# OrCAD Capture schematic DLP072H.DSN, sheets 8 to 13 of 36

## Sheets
8 PAGE10 - FPGA REGULATORS: size A3
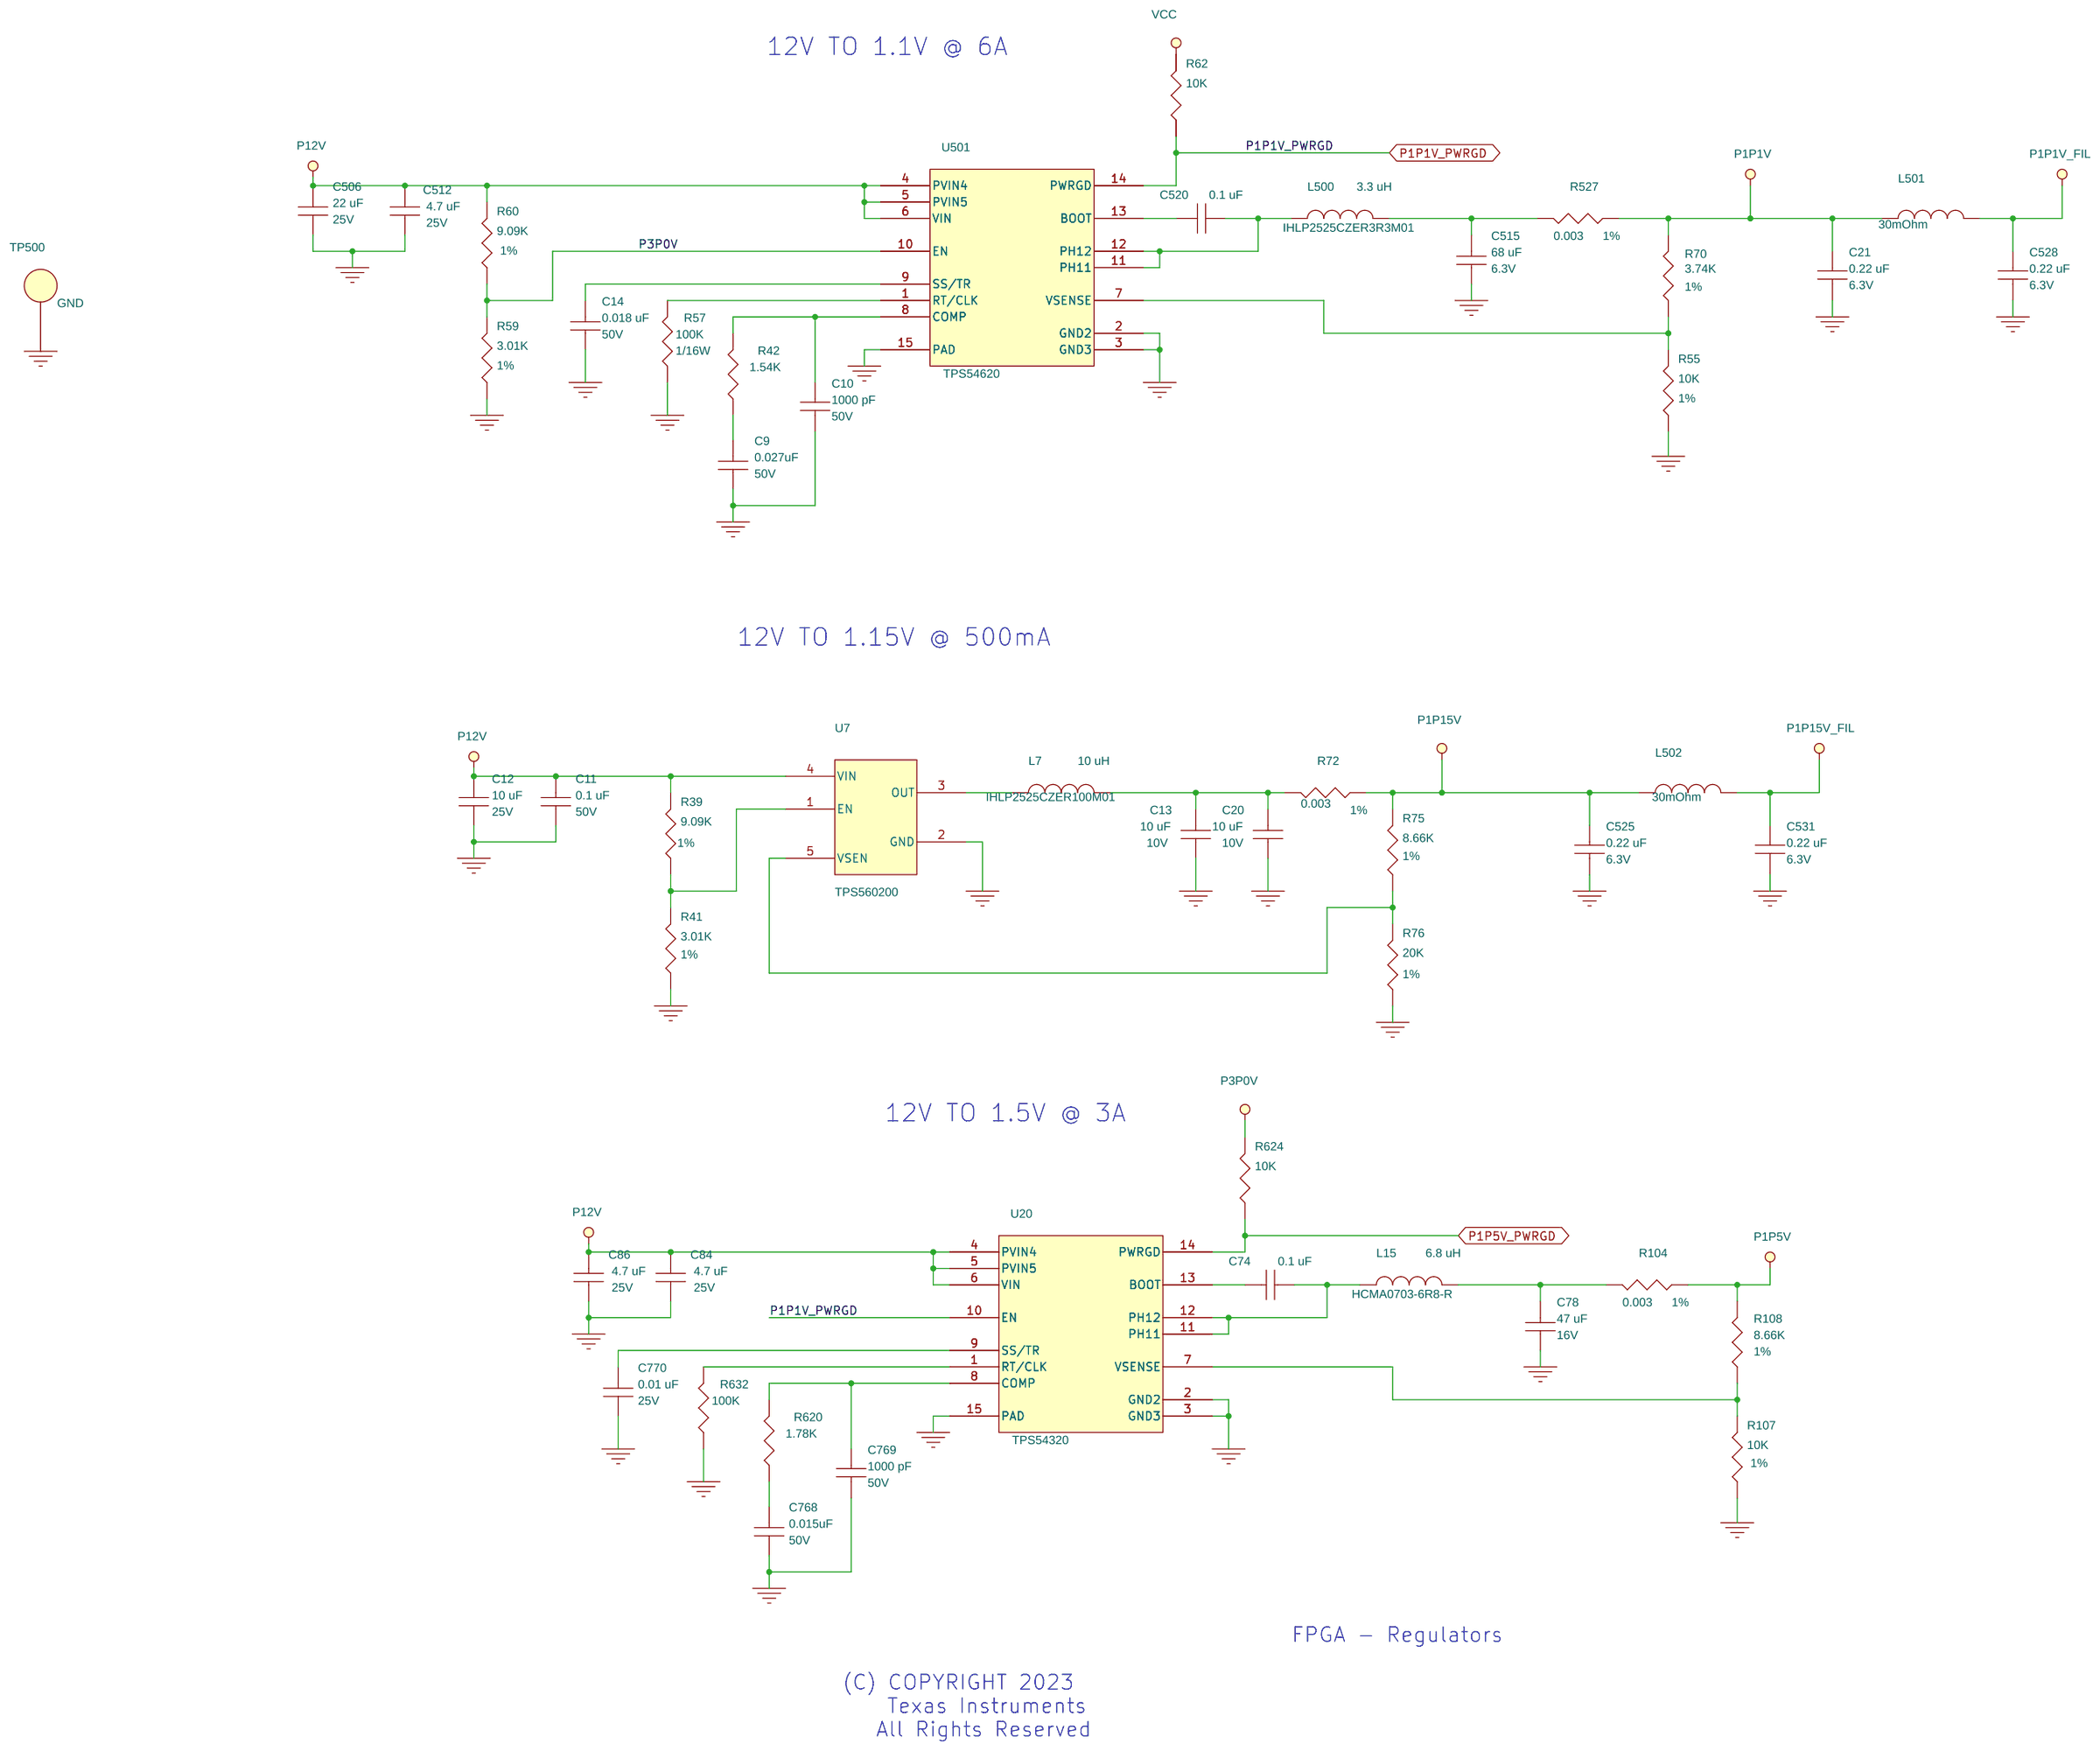
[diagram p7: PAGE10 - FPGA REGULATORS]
9 PAGE11 - FPGA REGULATORS: size A3
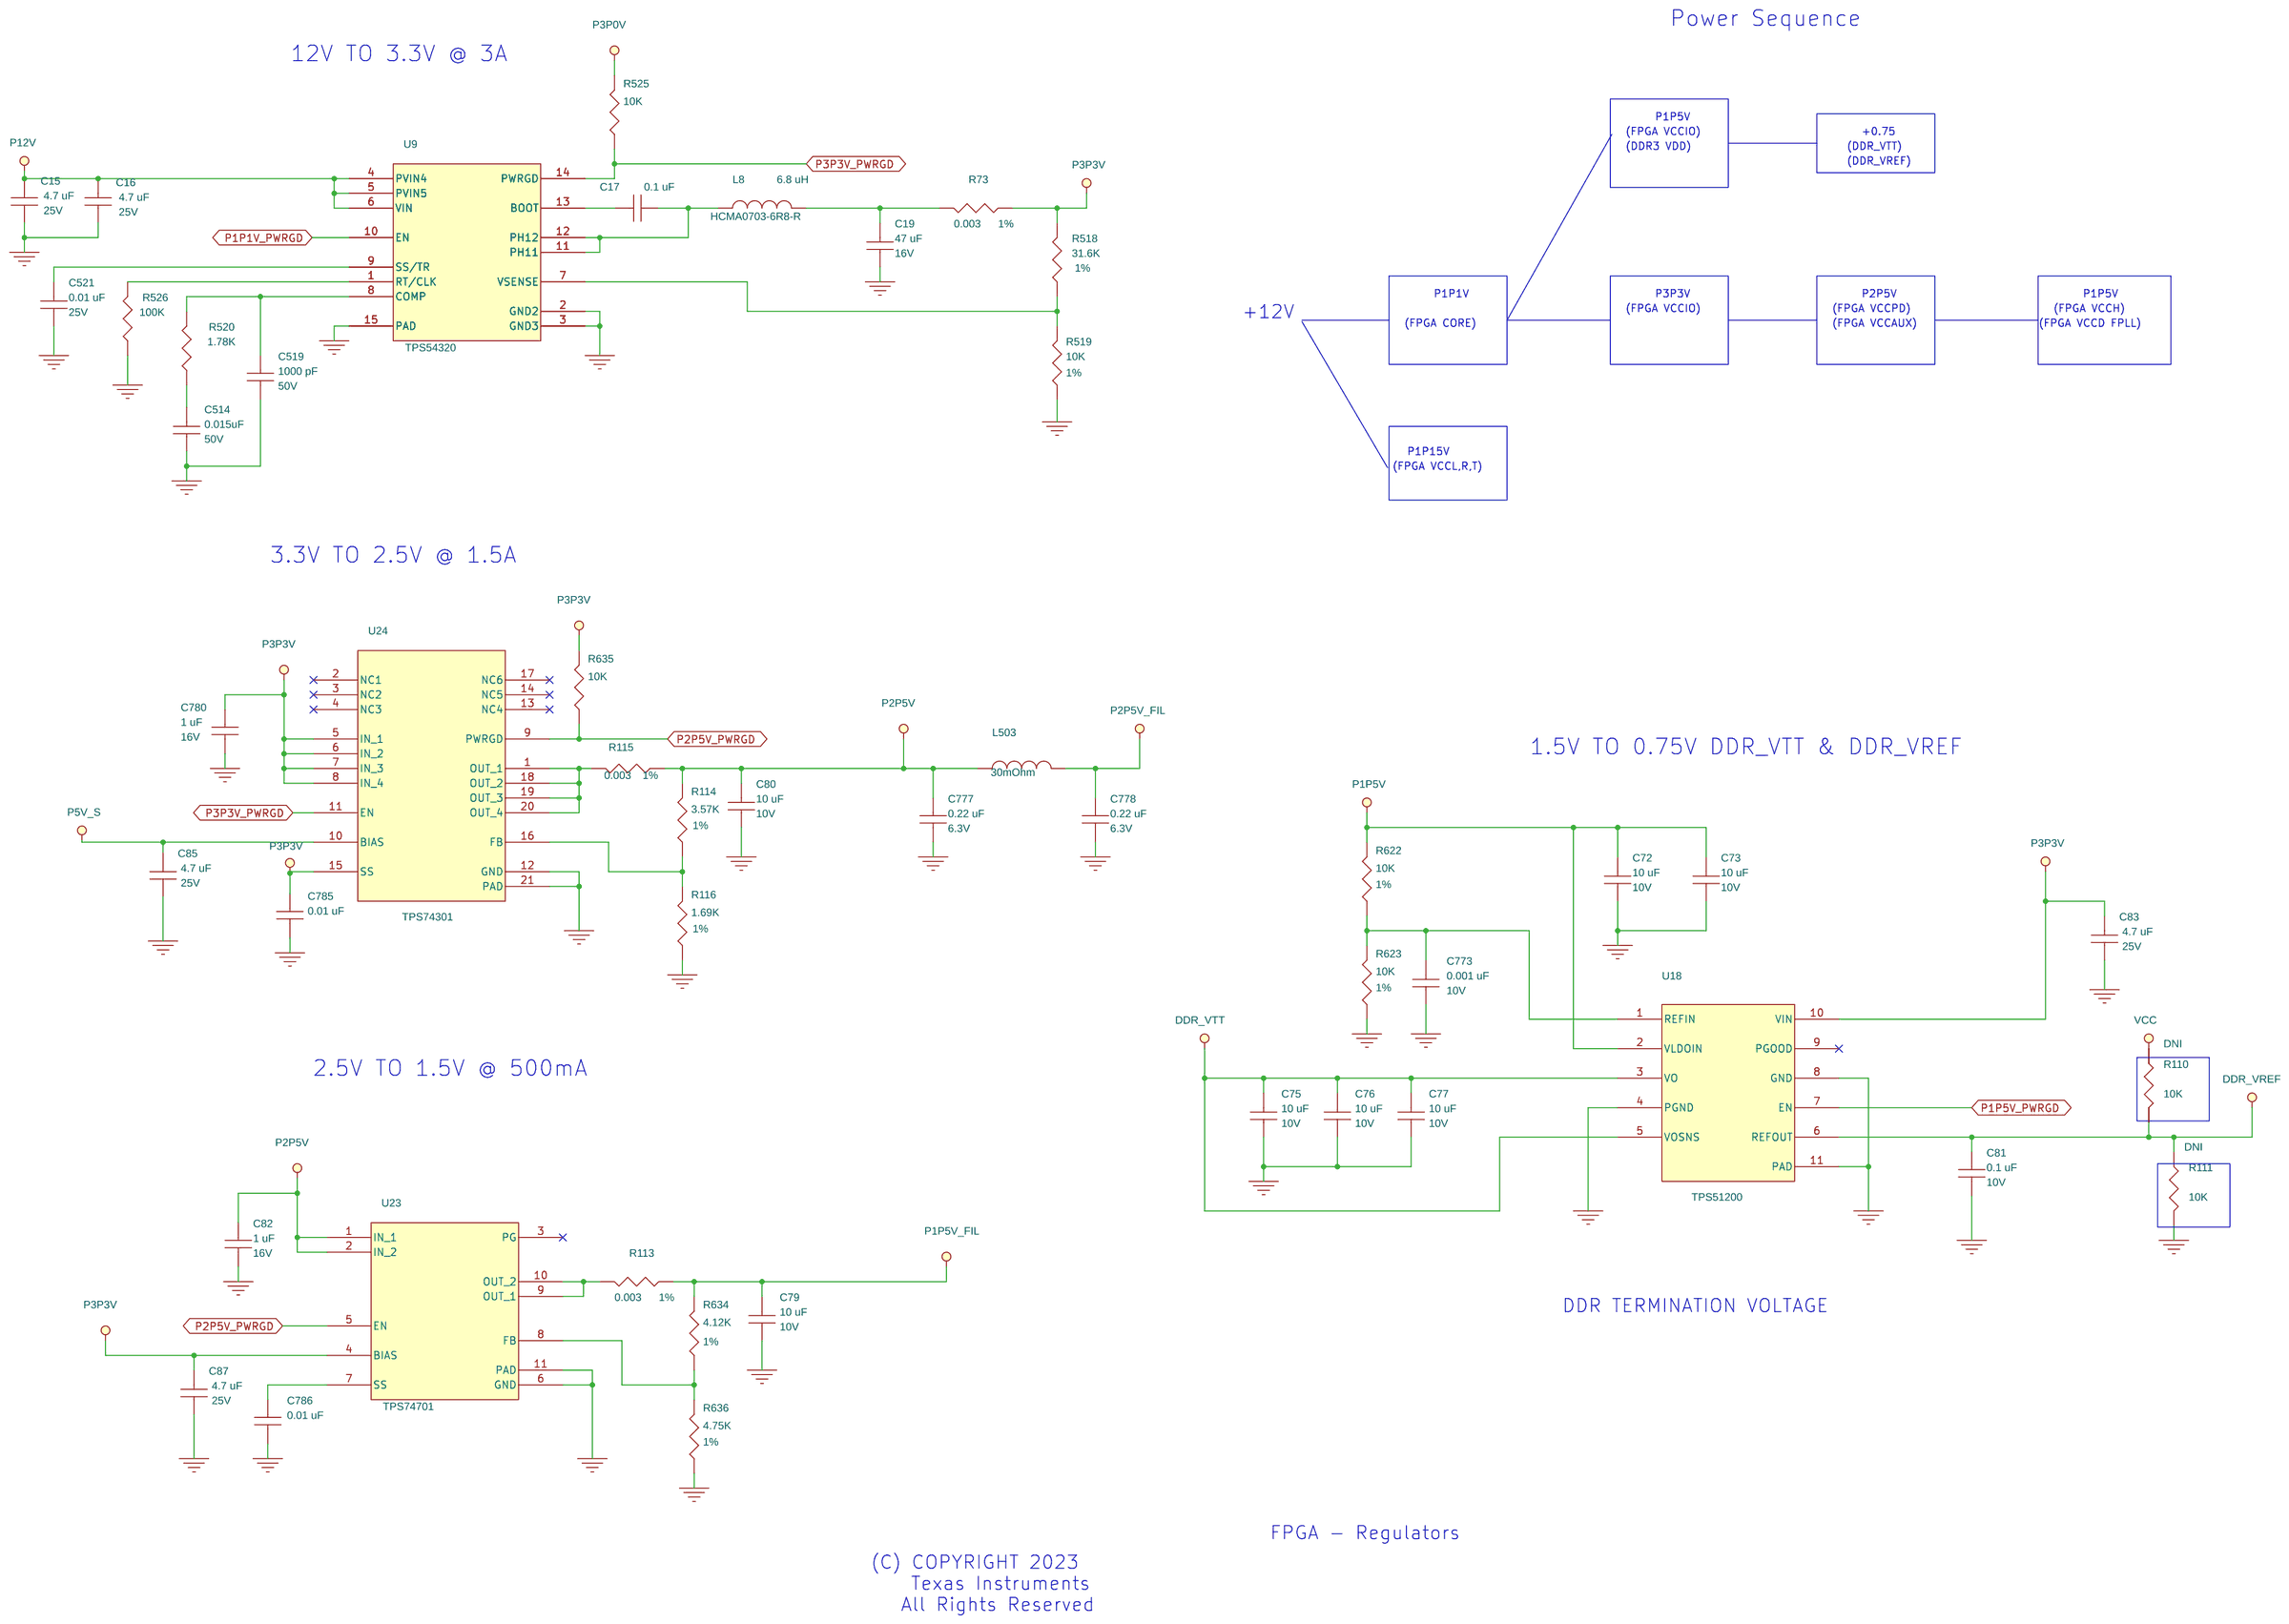
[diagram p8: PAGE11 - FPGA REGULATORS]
10 PAGE12 - FPGA GND: size A3
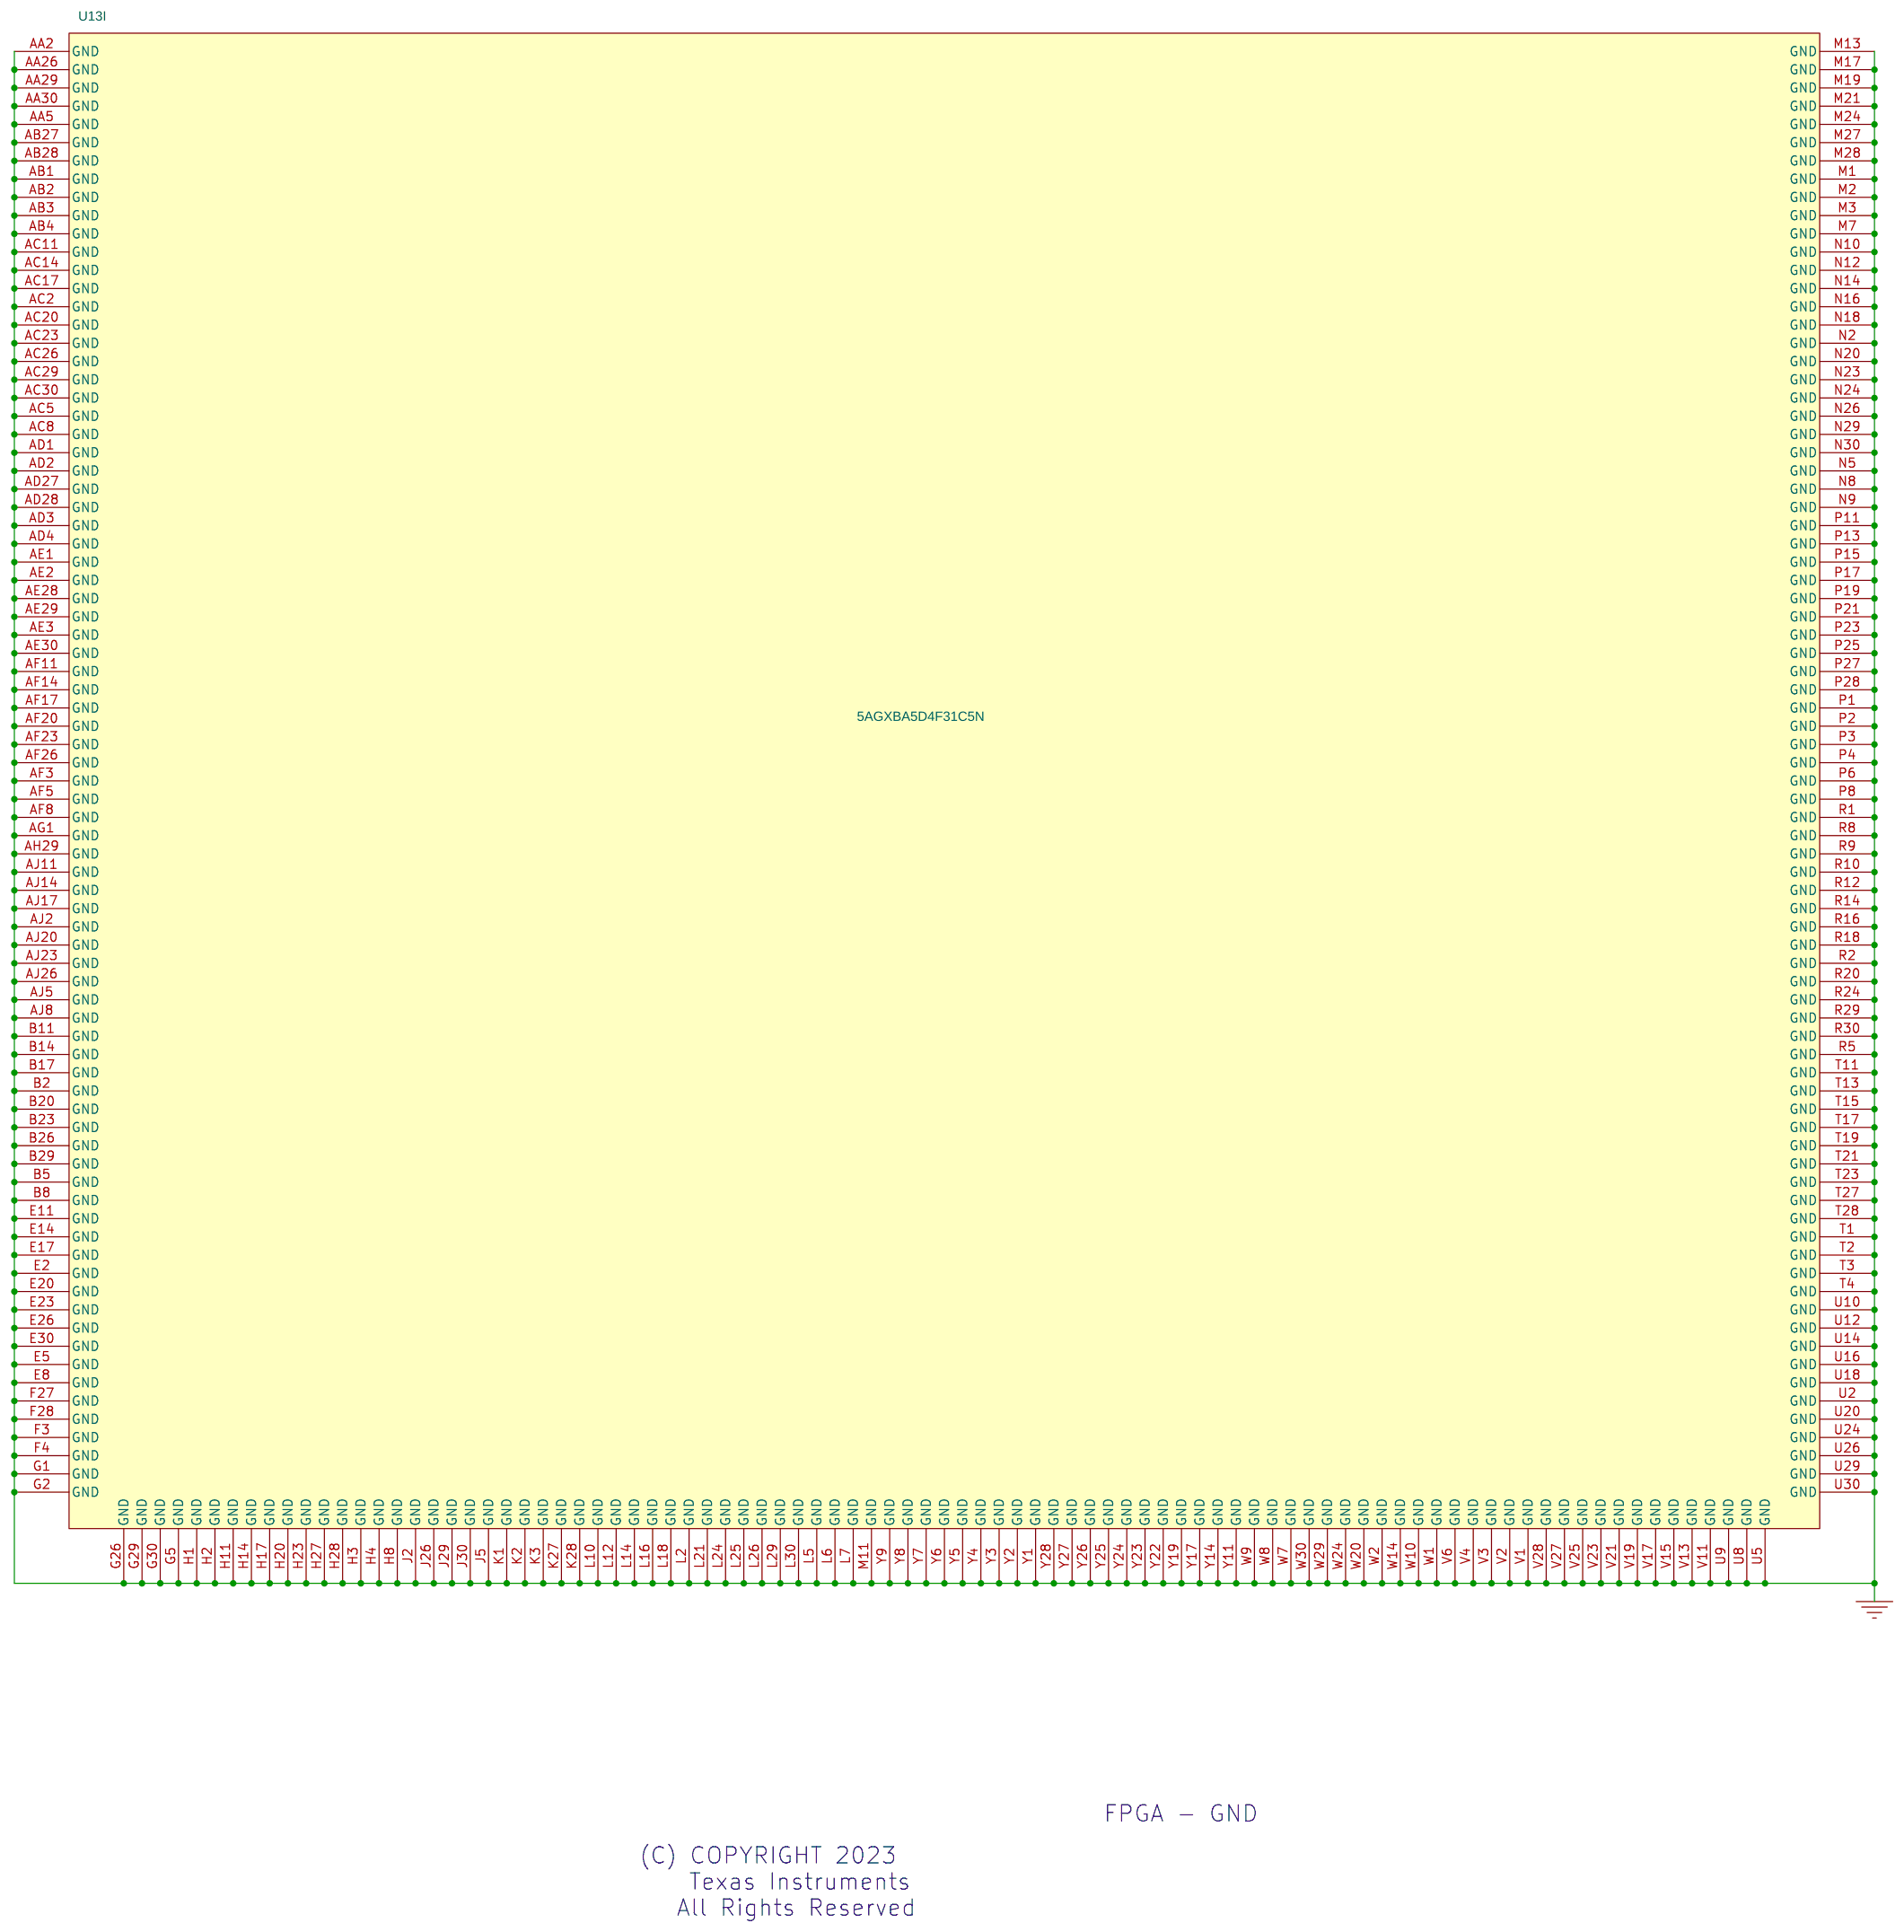
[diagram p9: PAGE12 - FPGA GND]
11 PAGE14 - DMD FLEX INTERFACE: size A3
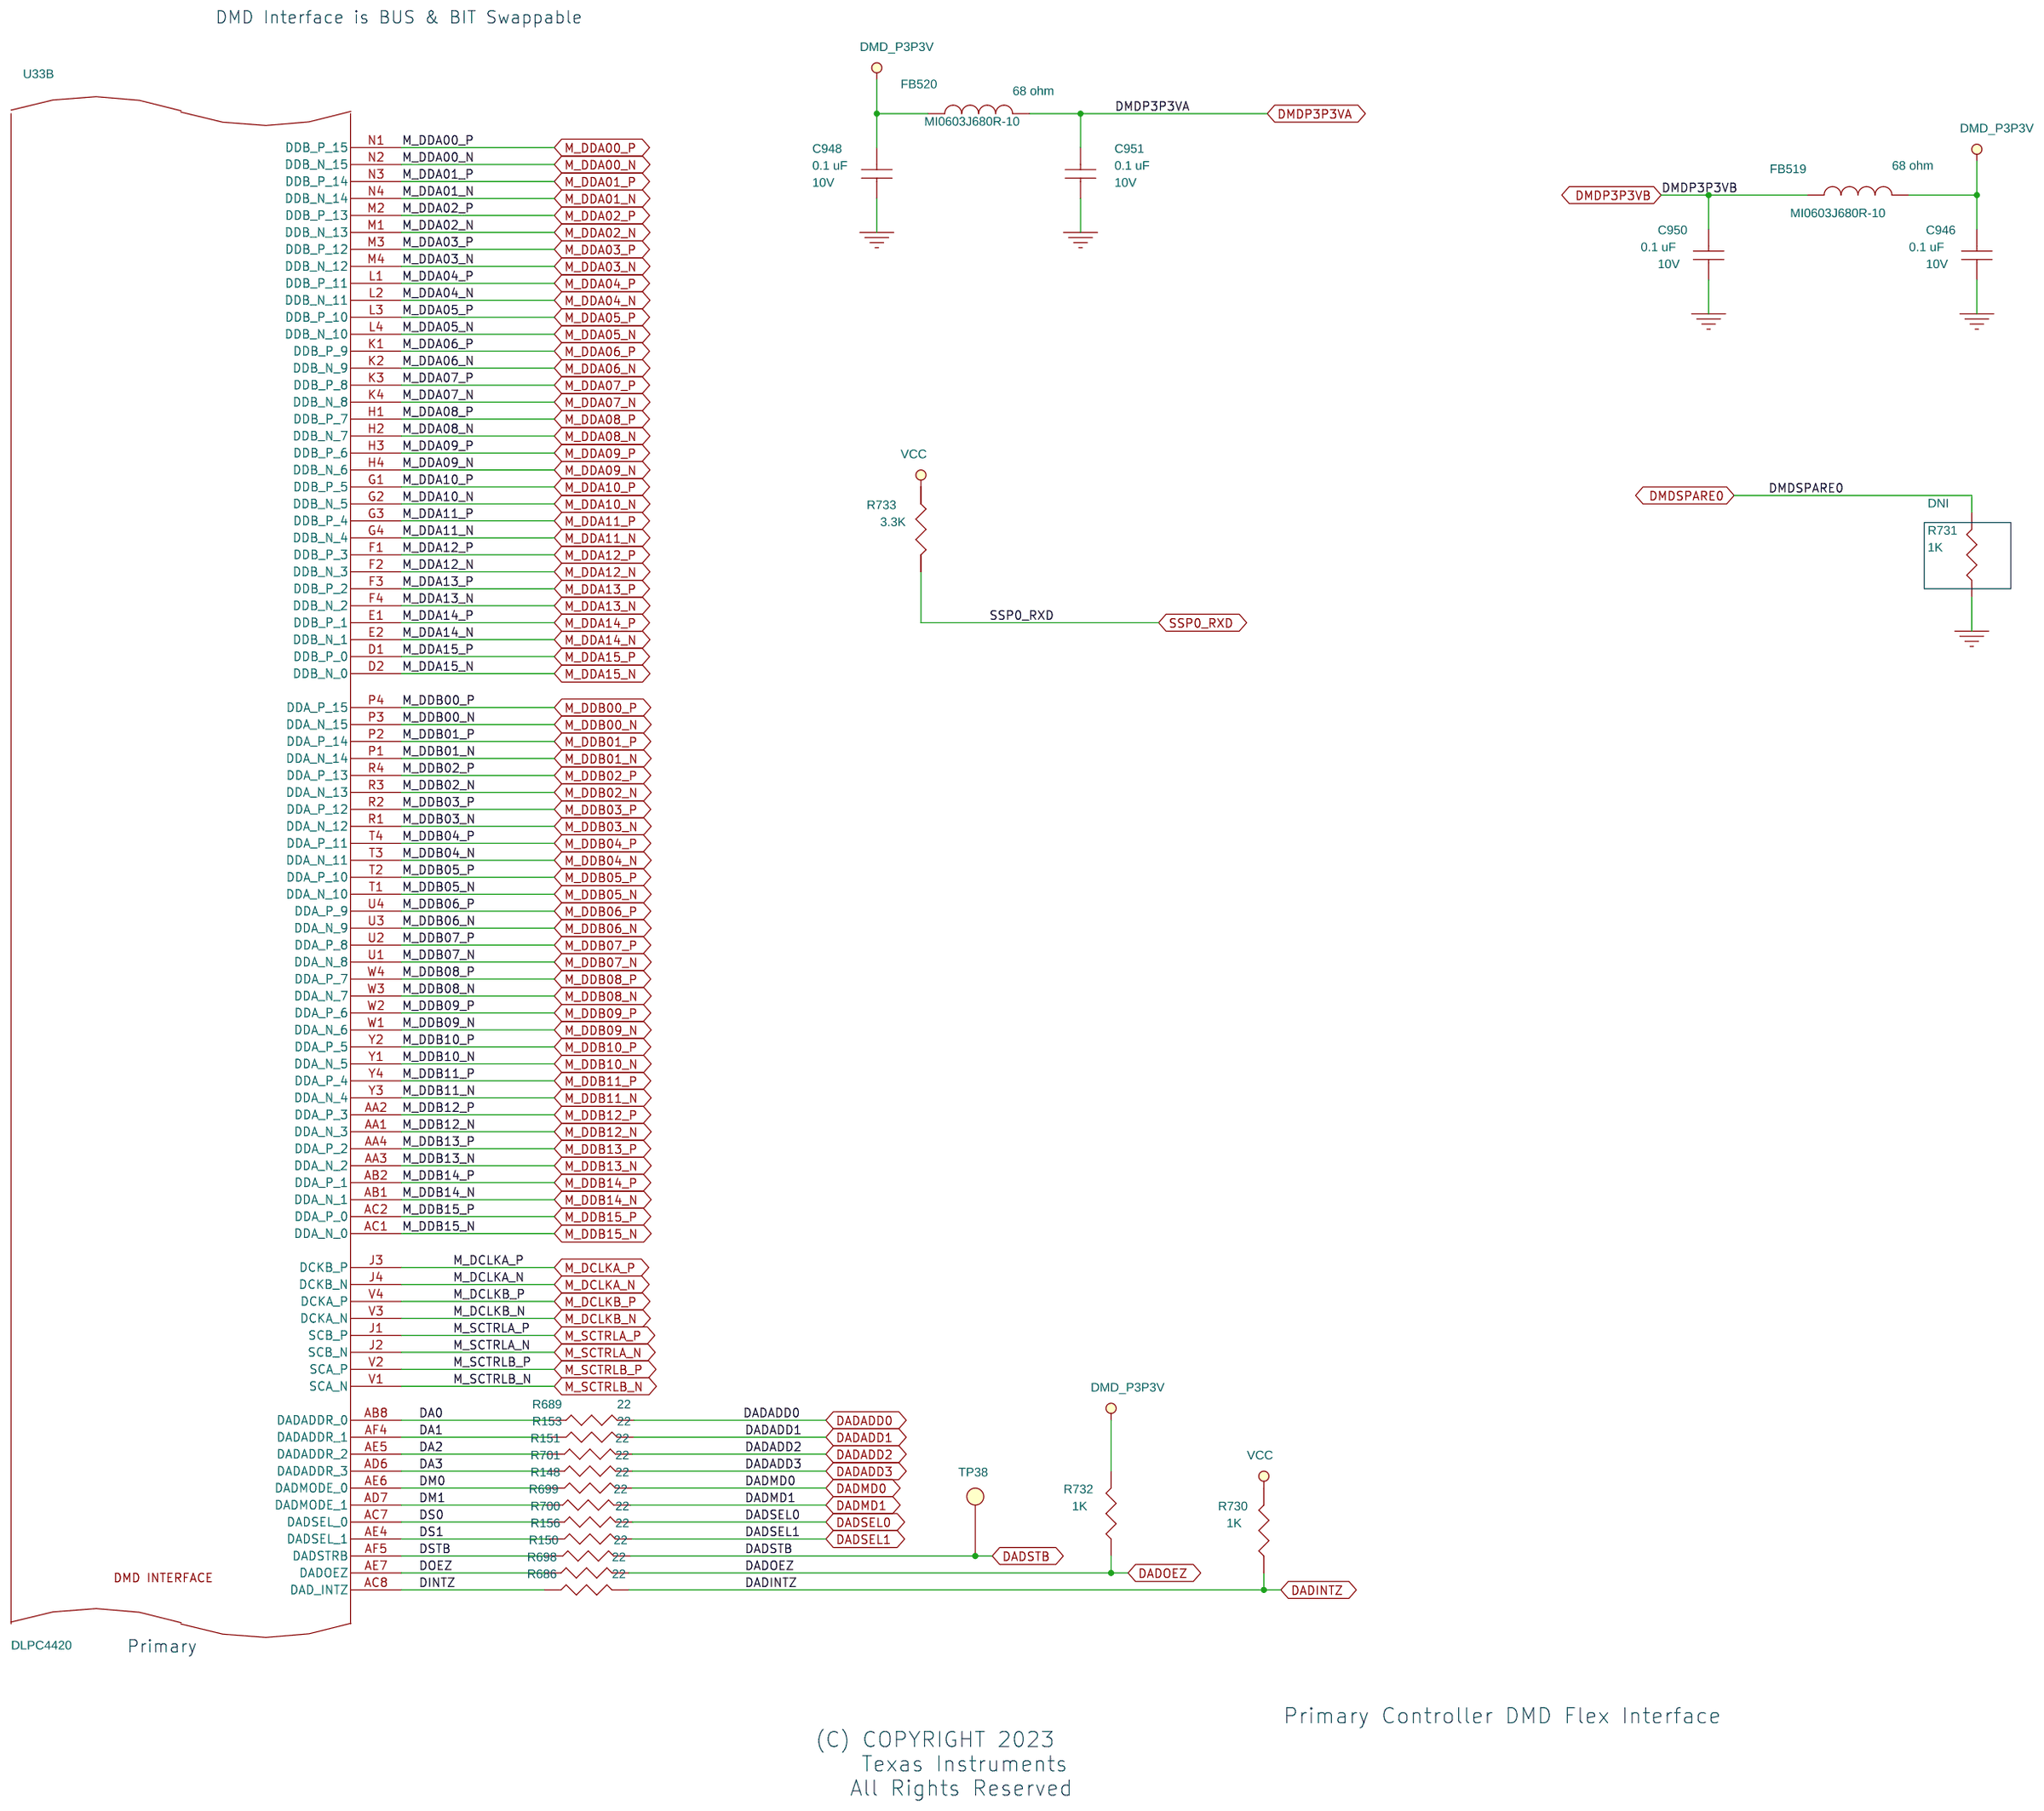
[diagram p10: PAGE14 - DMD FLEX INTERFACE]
12 PAGE16 - INPUT PWR & PMD1000: size A3
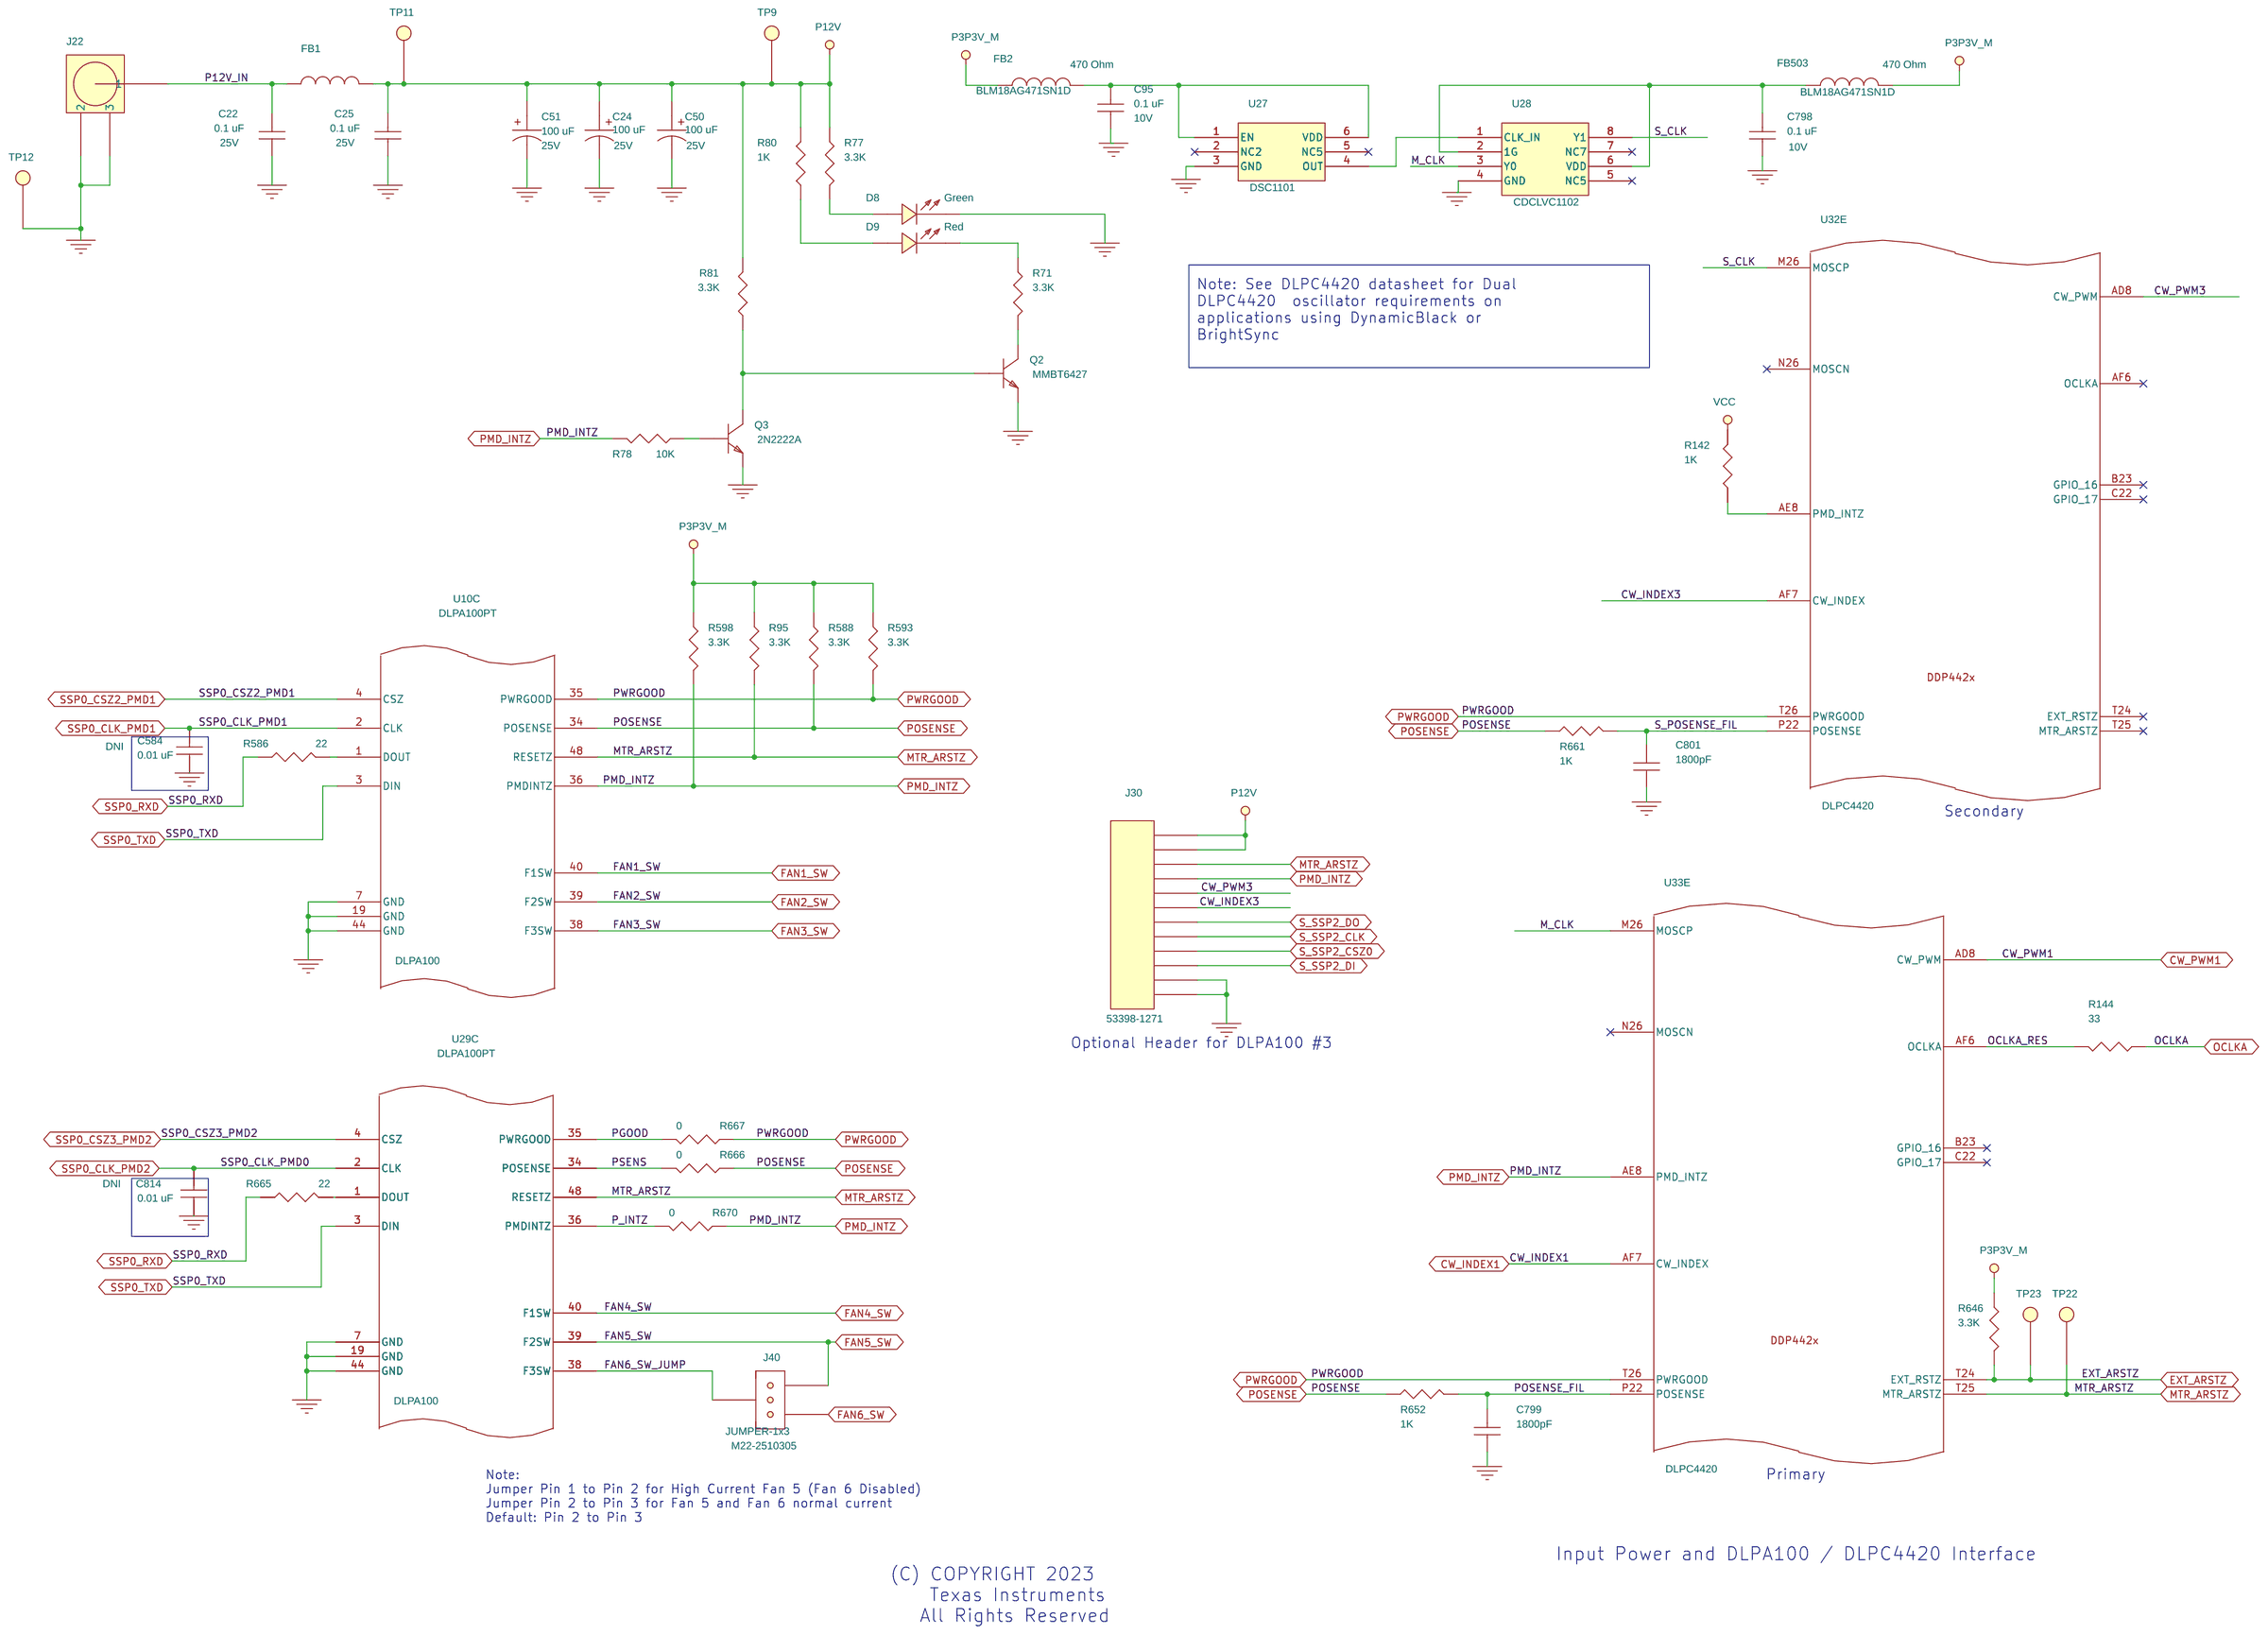
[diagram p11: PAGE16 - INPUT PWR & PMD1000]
13 PAGE17 - PMD1000 POWER SUPPLIES: size A3
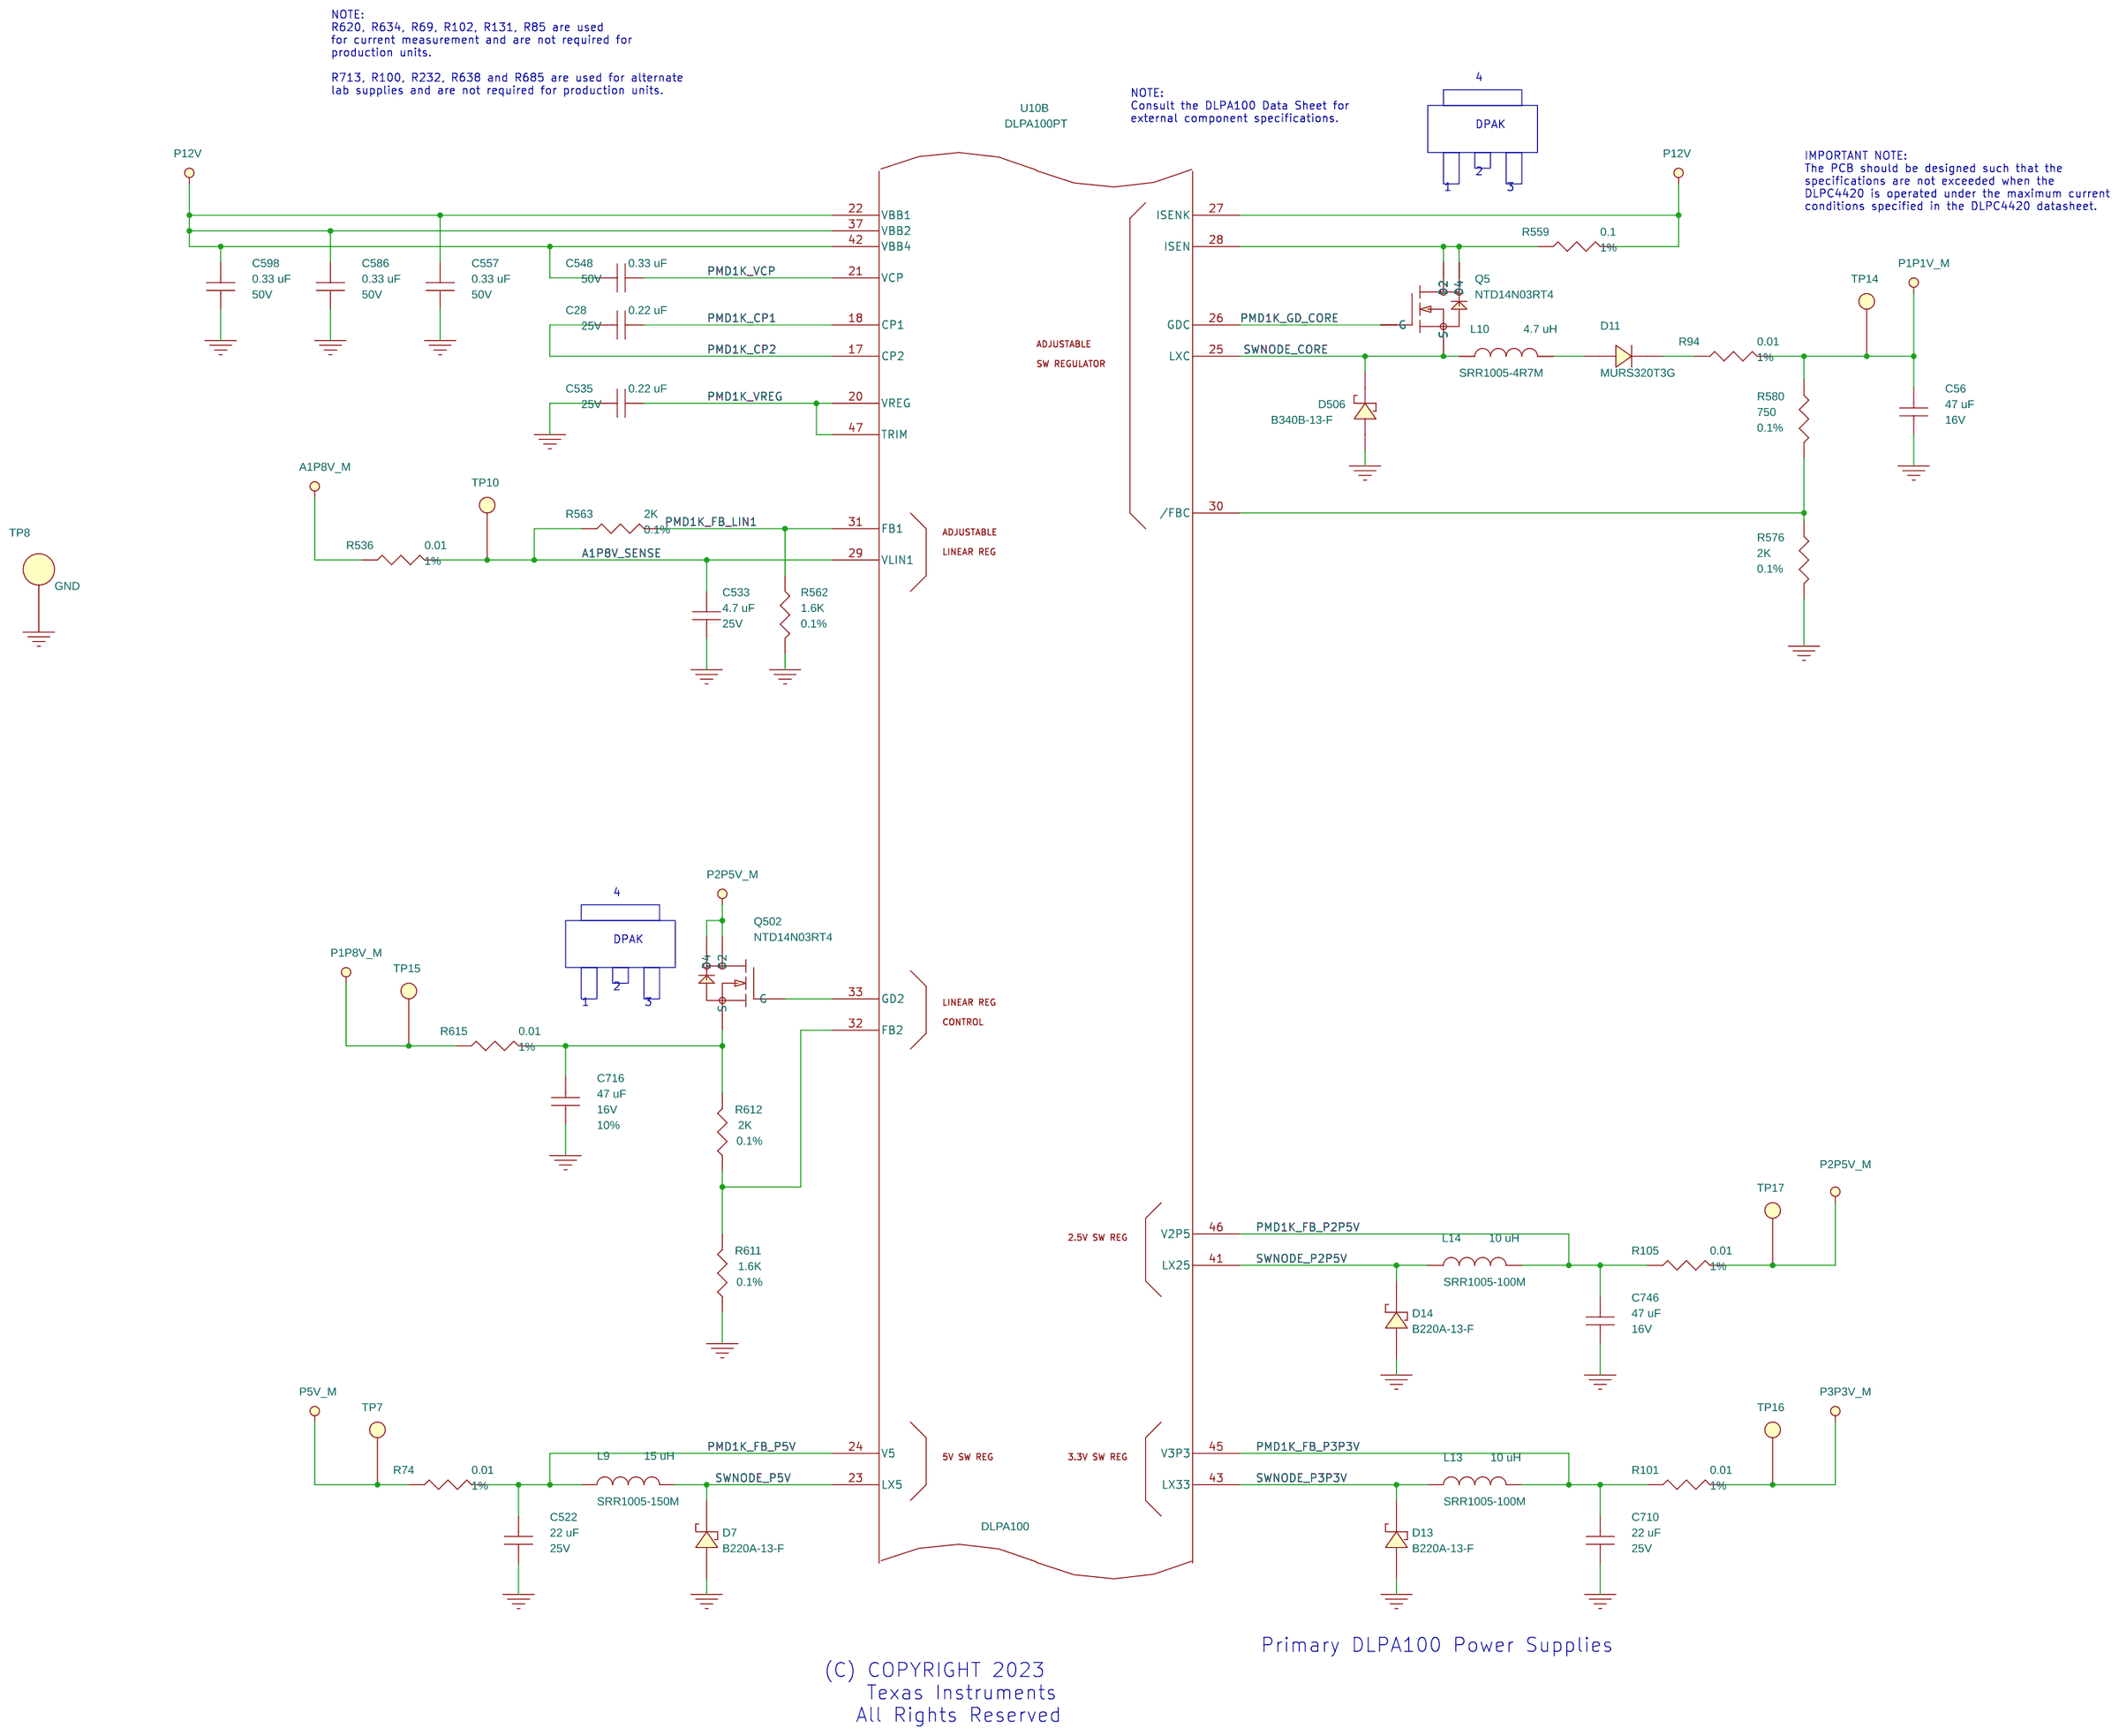
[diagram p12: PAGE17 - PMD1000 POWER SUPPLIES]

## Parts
sheet PAGE09 - FPGA POWER
U13  5AGXBA5D4F31C5N  [FBGA-896]  (sections A,B,C,D,E,F,G,H,I)
sheet PAGE10 - FPGA REGULATORS
C9  0.027uF  [CAP_0603]
C10  1000 pF  [CAP_0603]
C11  0.1 uF  [CAP_0805]
C12  10 uF  [CAP_0805]
C13  10 uF  [CAP_0805]
C14  0.018 uF  [CAP_0603]
C20  10 uF  [CAP_0805]
C21  0.22 uF  [CAP_0402]
C74  0.1 uF  [CAP_0402]
C78  47 uF  [CAP_1210]
C84  4.7 uF  [CAP_0805]
C86  4.7 uF  [CAP_0805]
C506  22 uF  [CAP_1210]
C512  4.7 uF  [CAP_0805]
C515  68 uF  [CAP_1210]
C520  0.1 uF  [CAP_0402]
C525  0.22 uF  [CAP_0402]
C528  0.22 uF  [CAP_0402]
C531  0.22 uF  [CAP_0402]
C768  0.015uF  [CAP_0603]
C769  1000 pF  [CAP_0603]
C770  0.01 uF  [CAP_0603]
L7  10 uH  [IND_IHLP_2525CZ]
L15  6.8 uH  [IND2-SPR7030_BOU]
L500  3.3 uH  [IND_IHLP_2525CZ]
L501  30mOhm  [IND_0805]
L502  30mOhm  [IND_0805]
R39  9.09K  [RES_0603]
R41  3.01K  [RES_0603]
R42  1.54K  [RES_0603]
R55  10K  [RES_0402]
R57  100K  [RES_0603]
R59  3.01K  [RES_0603]
R60  9.09K  [RES_0603]
R62  10K  [RES_0402]
R70  3.74K  [RES_0603]
R72  0.003  [RES_2512]
R75  8.66K  [RES_0603]
R76  20K  [RES_0603]
R104  0.003  [RES_2512]
R107  10K  [RES_0402]
R108  8.66K  [RES_0603]
R527  0.003  [RES_2512]
R620  1.78K  [RES_0603]
R624  10K  [RES_0402]
R632  100K  [RES_0603]
TP500  GND  [1p6mm_hole]
U7  TPS560200  [SOT23-5]
U20  TPS54320  [14-QFN]
U501  TPS54620  [14-QFN]
sheet PAGE11 - FPGA REGULATORS
C15  4.7 uF  [CAP_0805]
C16  4.7 uF  [CAP_0805]
C17  0.1 uF  [CAP_0402]
C19  47 uF  [CAP_1210]
C72  10 uF  [CAP_0805]
C73  10 uF  [CAP_0805]
C75  10 uF  [CAP_0805]
C76  10 uF  [CAP_0805]
C77  10 uF  [CAP_0805]
C79  10 uF  [CAP_0805]
C80  10 uF  [CAP_0805]
C81  0.1 uF  [CAP_0402]
C82  1 uF  [CAP_0603]
C83  4.7 uF  [CAP_0805]
C85  4.7 uF  [CAP_0805]
C87  4.7 uF  [CAP_0805]
C514  0.015uF  [CAP_0603]
C519  1000 pF  [CAP_0603]
C521  0.01 uF  [CAP_0603]
C773  0.001 uF  [CAP_0402]
C777  0.22 uF  [CAP_0402]
C778  0.22 uF  [CAP_0402]
C780  1 uF  [CAP_0603]
C785  0.01 uF  [CAP_0603]
C786  0.01 uF  [CAP_0603]
L8  6.8 uH  [IND2-SPR7030_BOU]
L503  30mOhm  [IND_0805]
R73  0.003  [RES_2512]
R110  10K  [RES_0603]
R111  10K  [RES_0603]
R113  0.003  [RES_2512]
R114  3.57K  [RES_0603]
R115  0.003  [RES_2512]
R116  1.69K  [RES_0603]
R518  31.6K  [RES_0603]
R519  10K  [RES_0402]
R520  1.78K  [RES_0603]
R525  10K  [RES_0402]
R526  100K  [RES_0603]
R622  10K  [RES_0402]
R623  10K  [RES_0402]
R634  4.12K  [RES_0603]
R635  10K  [RES_0402]
R636  4.75K  [RES_0402]
U9  TPS54320  [14-QFN]
U18  TPS51200  [SON10]
U23  TPS74701  [SON10]
U24  TPS74301  [20VQFN]
sheet PAGE14 - DMD FLEX INTERFACE
C946  0.1 uF  [CAP_0402]
C948  0.1 uF  [CAP_0402]
C950  0.1 uF  [CAP_0402]
C951  0.1 uF  [CAP_0402]
FB519  68 ohm  [FLTR_0603]
FB520  68 ohm  [FLTR_0603]
R148  22  [RES_0402]
R150  22  [RES_0402]
R151  22  [RES_0402]
R153  22  [RES_0402]
R156  22  [RES_0402]
R686  22  [RES_0402]
R689  22  [RES_0402]
R698  22  [RES_0402]
R699  22  [RES_0402]
R700  22  [RES_0402]
R701  22  [RES_0402]
R730  1K  [RES_0402]
R731  1K  [RES_0402]
R732  1K  [RES_0402]
R733  3.3K  [RES_0402]
TP38  Testpoint  [TP]
sheet PAGE16 - INPUT PWR & PMD1000
C22  0.1 uF  [CAP_0603]
C24  100 uF  [CAP-FK-V-CASEE_PAN]
C25  0.1 uF  [CAP_0603]
C50  100 uF  [CAP-FK-V-CASEE_PAN]
C51  100 uF  [CAP-FK-V-CASEE_PAN]
C95  0.1 uF  [CAP_0402]
C584  0.01 uF  [CAP_0603]
C798  0.1 uF  [CAP_0402]
C799  1800pF  [CAP_0603]
C801  1800pF  [CAP_0603]
C814  0.01 uF  [CAP_0603]
D8  Green  [D_0603]
D9  Red  [D_0603]
FB1  80 ohm  [IND_0805]
FB2  470 Ohm  [FLTR_0603]
FB503  470 Ohm  [FLTR_0603]
J22  POWER_12V_INPUT  [CUI_PJ-002AH]
J30  CON12  [CONN12-53398_MOLEX]
J40  JUMPER-1x3  [HDR1X3-TMM1030X-X-S_SAM]
Q2  MMBT6427  [SOT23AVXD]
Q3  2N2222A  [SOT23AVXD]
R71  3.3K  [RES_0402]
R77  3.3K  [RES_0402]
R78  10K  [RES_0402]
R80  1K  [RES_0402]
R81  3.3K  [RES_0402]
R95  3.3K  [RES_0402]
R142  1K  [RES_0402]
R144  33  [RES_0402]
R586  22  [RES_0402]
R588  3.3K  [RES_0402]
R593  3.3K  [RES_0402]
R598  3.3K  [RES_0402]
R646  3.3K  [RES_0402]
R652  1K  [RES_0402]
R661  1K  [RES_0402]
R665  22  [RES_0402]
R666  0  [RES_0402]
R667  0  [RES_0402]
R670  0  [RES_0402]
TP9  Testpoint  [TP]
TP11  Testpoint  [TP]
TP12  Testpoint  [TP]
TP22  Testpoint  [TP]
TP23  Testpoint  [TP]
U10  DLPA100  [QF48_PPAD]  (sections A,B,C)
U27  DSC1101  [6-DESCERA]
U28  CDCLVC1102  [TSSOP-8]
U29  DLPA100  [QF48_PPAD]  (sections A,B,C)
U32  DLPC4420  [BGA552-DDP4422_TI]  (sections A,B,C,D,E,F,G,H,I,J)
U33  DLPC4420  [BGA552-DDP4422_TI]  (sections A,B,C,D,E,F,G,H,I,J)
sheet PAGE17 - PMD1000 POWER SUPPLIES
C28  0.22 uF  [CAP_0805]
C56  47 uF  [CAP_1210]
C522  22 uF  [CAP_1210]
C533  4.7 uF  [CAP_0805]
C535  0.22 uF  [CAP_0805]
C548  0.33 uF  [CAP_0805]
C557  0.33 uF  [CAP_0805]
C586  0.33 uF  [CAP_0805]
C598  0.33 uF  [CAP_0805]
C710  22 uF  [CAP_1210]
C716  47 uF  [CAP_1210]
C746  47 uF  [CAP_1210]
D7  B220A  [DIO-SMA]
D11  MUR320T3G  [SMC_ST]
D13  B220A  [DIO-SMA]
D14  B220A  [DIO-SMA]
D506  B340B  [DIO-SMB]
L9  15 uH  [IND_SRR1005]
L10  4.7 uH  [IND_SRR1005]
L13  10 uH  [IND_SRR1005]
L14  10 uH  [IND_SRR1005]
Q5  NTD14N03RT4  [SM_TO_252_DPAK]
Q502  NTD14N03RT4  [SM_TO_252_DPAK]
R74  0.01  [RES_0805]
R94  0.01  [RES_0805]
R101  0.01  [RES_0805]
R105  0.01  [RES_0805]
R536  0.01  [RES_0805]
R559  0.1  [RES_0805]
R562  1.6K  [RES_0402]
R563  2K  [RES_0402]
R576  2K  [RES_0402]
R580  750  [RES_0402]
R611  1.6K  [RES_0402]
R612  2K  [RES_0402]
R615  0.01  [RES_0805]
TP7  Testpoint  [TP]
TP8  GND  [1p6mm_hole]
TP10  Testpoint  [TP]
TP14  Testpoint  [TP]
TP15  Testpoint  [TP]
TP16  Testpoint  [TP]
TP17  Testpoint  [TP]

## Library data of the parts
U13 = 5AGXMA5GF31: IC, FPGA; MFG: ALTERA
C9 = CAP_NP: Capacitor; CCA: 12; MFG: AVX; Part Number: 06035C273KAT2A; RATING: 50V; TOLERANCE: 10%; Type: X7R
C10 C519 C769 = CAP_NP: Capacitor; ALT_SYMBOLS: 0402-1MM; CCA: 116; MFG: KEMET; Part Number: C0603C102K5RAC7867; RATING: 50V; TOLERANCE: 10%; Type: X7R
C11 = CAP_NP: Capacitor; CCA: 9; MFG: AVX; Part Number: 08055C104MAT2A; RATING: 50V; TOLERANCE: 10%; Type: X7R
C12 = CAP_NP: Capacitor; CCA: 119; MFG: MURATA; Part Number: GRM21BR61E106KA73L; RATING: 25V; TOLERANCE: 10%; Type: X5R
C13 C20 C72 C73 C75-C77 C79 C80 = CAP_NP: Capacitor; CCA: 112; MFG: MURATA; Part Number: GRM21BR71A106KE51L; RATING: 10V; TOLERANCE: 10%; Type: X7R
C14 = CAP_NP: Capacitor; CCA: 11; MFG: AVX CORP; Part Number: 06035C183KAT2A; RATING: 50V; TOLERANCE: 10%; Type: X7R
C21 C525 C528 C531 C777 C778 = CAP_NP: Capacitor; CCA: 39; MFG: SAMSUNG; Part Number: CL05A224KQ5NNNC; RATING: 6.3V; TOLERANCE: 10%; Type: X5R
C17 C74 C81 C520 = CAP_NP: Capacitor; CCA: 34; MFG: KEMET; Part Number: C0402C104K8RACTU; RATING: 10V; TOLERANCE: 10%; Type: X7R
C19 C78 = CAP_NP: Capacitor; CCA: 115; MFG: SAMSUNG; Part Number: CL32A476KOJNNNE; RATING: 16V; TOLERANCE: 10%; Type: X5R
C15 C16 C83-C87 C512 = CAP_NP: Capacitor; CCA: 42; MFG: TDK; Part Number: C2012X7R1E475K125AB; RATING: 25V; TOLERANCE: 10%; Type: X7R
C506 = CAP_NP: Capacitor; CCA: 16; MFG: AVX; Part Number: 12103D226KAT2A; RATING: 25V; TOLERANCE: 10%; Type: X5R
C515 = CAP_NP: Capacitor; CCA: 44; MFG: TDK; Part Number: C3216X5R0J686M160AB; RATING: 6.3V; TOLERANCE: 20%; Type: X5R
C514 C768 = CAP_NP: Capacitor; CCA: 10; MFG: AVX; Part Number: 06035C153KAT2A; RATING: 50V; TOLERANCE: 10%; Type: X7R
C521 C770 C785 C786 = CAP_NP: Capacitor; CCA: 47; MFG: YAGEO; Part Number: CC0603KRX7R8BB103; RATING: 25V; TOLERANCE: 10%; Type: X7R
L7 = INDUCTOR: Inductor; CCA: 125; ICA_MFR_NAME: STEWARD; ICA_PARTNUM: $$731362$$MI0603J680R-10; MFG: VISHAY; Part Number: IHLP2525CZER100M01; RATING: 6A
L8 L15 = INDUCTOR: Inductor; CCA: 153; ICA_MFR_NAME: STEWARD; ICA_PARTNUM: $$731362$$MI0603J680R-10; MFG: EATON; Part Number: HCMA0703-6R8-R; RATING: 4.5A
L500 = INDUCTOR: Inductor; CCA: 124; ICA_MFR_NAME: STEWARD; ICA_PARTNUM: $$731362$$MI0603J680R-10; MFG: VISHAY; Part Number: IHLP2525CZER3R3M01; RATING: 6A
L501-L503 = INDUCTOR_SM: Ferrite; CCA: 31; MFG: MURATA; Part Number: BLM21PG121SN1D; Rating: 3A; Tolerance: 25%
R39 R60 = R: Resistor; ALT_SYMBOLS: 0402-1MM; CCA: 92; ICA_MFR_NAME: PANASONIC; ICA_PARTNUM: $$1785048$$ERJ-3GSYJ102; MFG: PANASONIC; Part Number: ERJ-3EKF9091V; RATING: 1/10W; TOLERANCE: 1%
R41 R59 = R: Resistor; ALT_SYMBOLS: 0402-1MM; CCA: 81; ICA_MFR_NAME: PANASONIC; ICA_PARTNUM: $$1785048$$ERJ-3GSYJ102; MFG: PANASONIC; Part Number: ERJ-3EKF3011V; RATING: 1/10W; TOLERANCE: 1%
R42 = R: Resistor; CCA: 77; ICA_MFR_NAME: PANASONIC; ICA_PARTNUM: $$1785048$$ERJ-3GSYJ102; MFG: PANASONIC; Part Number: ERJ-3EKF1541V; RATING: 1/10W; TOLERANCE: 1%
R55 R107 R519 R622 R623 = R: Resistor; ALT_SYMBOLS: 0402-1MM; CCA: 72; ICA_MFR_NAME: PANASONIC; ICA_PARTNUM: $$1785048$$ERJ-3GSYJ102; MFG: PANASONIC; Part Number: ERJ-2RKF1002X; RATING: 1/10W; TOLERANCE: 1%
R57 R526 R632 = R: Resistor; CCA: 3; ICA_MFR_NAME: PANASONIC; ICA_PARTNUM: $$1785048$$ERJ-3GSYJ102; MFG: TE CONNECTIVITY; Part Number: 5-1879338-6; RATING: 1/16W; TOLERANCE: 1%
R62 R525 R624 R635 = R: Resistor; ALT_SYMBOLS: 0402-1MM; CCA: 65; ICA_MFR_NAME: PANASONIC; ICA_PARTNUM: $$1785048$$ERJ-3GSYJ102; MFG: PANASONIC; Part Number: ERJ-2GEJ103X; RATING: 1/10W; TOLERANCE: 5%
R70 = R: Resistor; CCA: 85; ICA_MFR_NAME: PANASONIC; ICA_PARTNUM: $$1785048$$ERJ-3GSYJ102; MFG: PANASONIC; Part Number: ERJ-3EKF3741V; RATING: 1/10W; TOLERANCE: 1%
R72 R73 R104 R113 R115 R527 = R: Resistor; ALT_SYMBOLS: 0402-1MM; CCA: 141; ICA_MFR_NAME: PANASONIC; ICA_PARTNUM: $$1785048$$ERJ-3GSYJ102; MFG: ROHM; Part Number: PMR100HZPFV3L00; RATING: 2W; TOLERANCE: 1%
R75 = R: Resistor; ALT_SYMBOLS: 0402-1MM; CCA: 91; ICA_MFR_NAME: PANASONIC; ICA_PARTNUM: $$1785048$$ERJ-3GSYJ102; MFG: PANASONIC; Part Number: ERJ-3EKF8661V; RATING: 1/10W; TOLERANCE: 1%
R76 = R: Resistor; ALT_SYMBOLS: 0402-1MM; CCA: 80; ICA_MFR_NAME: PANASONIC; ICA_PARTNUM: $$1785048$$ERJ-3GSYJ102; MFG: PANASONIC; Part Number: ERJ-3EKF2002V; RATING: 1/10W; TOLERANCE: 1%
R108 = R: Resistor; CCA: 91; ICA_MFR_NAME: PANASONIC; ICA_PARTNUM: $$1785048$$ERJ-3GSYJ102; MFG: PANASONIC; Part Number: ERJ-3EKF8661V; RATING: 1/10W; TOLERANCE: 1%
R520 R620 = R: Resistor; CCA: 79; ICA_MFR_NAME: PANASONIC; ICA_PARTNUM: $$1785048$$ERJ-3GSYJ102; MFG: PANASONIC; Part Number: ERJ-3EKF1781V; RATING: 1/10W; TOLERANCE: 1%
TP8 TP500 = TP_LOOP: TP, Loop; MFG: Keystone; Part Number: 5011
U7 = TPS560200_0: IC, SW ADJ Voltage Reg; MFG: TI; Part Number: TPS560200DBVR; RATING: 500 mA
U9 U20 = TPS54320_0: IC, SW ADJ Voltage Reg; CCA: 166; MFG: TI; Part Number: TPS54320RHLR; RATING: 3 A
U501 = TPS54620_0: IC, SW ADJ Voltage Reg; CCA: 168; MFG: TI; Part Number: TPS54620RHLR; RATING: 6 A; SOURCE: DIGI 296-28831-1-ND
C82 C780 = CAP_NP: Capacitor; CCA: 8; MFG: AVX; Part Number: 06033D105KAT2A; RATING: 16V; TOLERANCE: 10%; Type: X5R
C773 = CAP_NP: Capacitor; CCA: 32; MFG: KEMET; Part Number: C0402C102K8RACTU; RATING: 10V; TOLERANCE: 10%; Type: X7R
R110 R111 = R: Resistor; ALT_SYMBOLS: 0402-1MM; DNI: DNI; ICA_MFR_NAME: PANASONIC; ICA_PARTNUM: $$1785048$$ERJ-3GSYJ102; MFG: PANASONIC; Part Number: ERJ-3EKF1002V; RATING: 1/10W; TOLERANCE: 1%
R114 = R: Resistor; ALT_SYMBOLS: 0402-1MM; CCA: 84; ICA_MFR_NAME: PANASONIC; ICA_PARTNUM: $$1785048$$ERJ-3GSYJ102; MFG: PANASONIC; Part Number: ERJ-3EKF3571V; RATING: 1/10W; TOLERANCE: 1%
R116 = R: Resistor; ALT_SYMBOLS: 0402-1MM; CCA: 78; ICA_MFR_NAME: PANASONIC; ICA_PARTNUM: $$1785048$$ERJ-3GSYJ102; MFG: PANASONIC; Part Number: ERJ-3EKF1691V; RATING: 1/10W; TOLERANCE: 1%
R518 = R: Resistor; CCA: 83; ICA_MFR_NAME: PANASONIC; ICA_PARTNUM: $$1785048$$ERJ-3GSYJ102; MFG: PANASONIC; Part Number: ERJ-3EKF3162V; RATING: 1/10W; TOLERANCE: 1%
R634 = R: Resistor; ALT_SYMBOLS: 0402-1MM; CCA: 87; ICA_MFR_NAME: PANASONIC; ICA_PARTNUM: $$1785048$$ERJ-3GSYJ102; MFG: PANASONIC; Part Number: ERJ-3EKF4121V; RATING: 1/10W; TOLERANCE: 1%
R636 = R: Resistor; ALT_SYMBOLS: 0402-1MM; CCA: 53; ICA_MFR_NAME: PANASONIC; ICA_PARTNUM: $$1785048$$ERJ-3GSYJ102; MFG: VISHAY/DALE; Part Number: ERJ-2RKF4751X; RATING: 1/10W; TOLERANCE: 1%
U18 = TPS51200_1: IC, Voltage Reg DDR3; CCA: 165; MFG: TI; Part Number: TPS51200DRCR; SOURCE: DIGI 296-26978-2-ND
U23 = TPS74701_1: IC, LDO ADJ Voltage Reg; CCA: 170; MFG: TI; Part Number: TPS74701DRCR; RATING: 0.5 A; SOURCE: DIGI 296-22987-2-ND
U24 = TPS74301_0: IC, LDO ADJ Voltage Reg; CCA: 169; MFG: TI; Part Number: TPS74301RGWT; RATING: 1.5 A
C95 C798 C946 C948 C950 C951 = CAP_NP: Capacitor; CCA: 34; MFG: KEMET; Part Number: C0402C104K8RACTU; RATING: 10V; SOURCE: DIGI 399-3520-1-ND; TOLERANCE: 10%; Type: X7R
FB519 FB520 = INDUCTOR: Ferrite; CCA: 132; ICA_MFR_NAME: STEWARD; ICA_PARTNUM: $$731362$$MI0603J680R-10; MFG: STEWARD; Part Number: MI0603J680R-10; RATING: 1A, 100MHz; SOURCE: DIGI 240-2372-1-ND
R148 R150 R151 R153 R156 R586 R665 R686 R689 R698-R701 = R: Resistor; CCA: 143; MFG: YAGEO; Part Number: RC0402FR-0722RL; RATING: 1/16W; SOURCE: DIGI 311-22.0LRTR-ND; TOLERANCE: 1%
R80 R142 R652 R661 R730 R732 = R: Resistor; CCA: 64; ICA_MFR_NAME: PANASONIC; ICA_PARTNUM: $$1785048$$ERJ-3GSYJ102; MFG: PANASONIC; Part Number: ERJ-2GEJ102X; RATING: 1/10W; SOURCE: DIGI P1.0KJCT-ND; TOLERANCE: 5%
R731 = R: Resistor; CCA: 64; DNI: DNI; ICA_MFR_NAME: PANASONIC; ICA_PARTNUM: $$1785048$$ERJ-3GSYJ102; MFG: PANASONIC; Part Number: ERJ-2GEJ102X; RATING: 1/10W; SOURCE: DIGI P1.0KJCT-ND; TOLERANCE: 5%
R71 R77 R81 R95 R588 R593 R598 R646 R733 = R: Resistor; CCA: 68; ICA_MFR_NAME: PANASONIC; ICA_PARTNUM: $$1785048$$ERJ-3GSYJ102; MFG: PANASONIC; Part Number: ERJ-2GEJ332X; RATING: 1/10W; SOURCE: DIGI P3.3KJCT-ND; TOLERANCE: 5%
TP7 TP9-TP12 TP14-TP17 TP22 TP23 TP38 = Testpoint: Test point
C22 C25 = CAP_NP: Capacitor; CCA: 48; MFG: KEMET; Part Number: C0603C104K3RACTU; RATING: 25V; SOURCE: DIGI PCC2277CT-ND; TOLERANCE: 10%; Type: X7R
C24 C50 C51 = CAP_POL: Capacitor; CCA: 56; MFG: PANASONIC; Part Number: EEE-FK1E101P; RATING: 25V; SOURCE: DIGI PCE3796CT-ND; TOLERANCE: 20%
C584 C814 = CAP_NP: Capacitor; CCA: 47; DNI: DNI; MFG: YAGEO; Part Number: CC0603KRX7R8BB103; RATING: 25V; TOLERANCE: 10%; Type: X7R
C799 C801 = CAP_NP: Capacitor; CCA: 47; MFG: AVX; Part Number: 06035C182KAT2A; RATING: 50V; TOLERANCE: 10%; Type: X7R
D8 = LED_GREEN_CLEAR_0603: LED; Part Number: LTST-C190GKT
D9 = LED_GREEN_CLEAR_0603: LED; MFG Part Number: LTST-C191KRKT; Part Number: LTST-C191KRKT
FB1 = FERRITE: Ferrite; CCA: 123; MFG: STEWARD; Part Number: HI0805R800R-10; RATING: 5A, 100MHz; SOURCE: DIGI 240-2395-1-ND
FB2 FB503 = INDUCTOR: Ferrite; CCA: 30; ICA_MFR_NAME: STEWARD; ICA_PARTNUM: $$731362$$MI0603J680R-10; MFG: MURATA; Part Number: BLM18AG471SN1D; RATING: 500mA, 100MHz; SOURCE: DIGI 490-1013-1-ND
J22 = POWER_12V_INPUT_0: Connector, Power Jack; CCA: 139; MFG: CUI; Part Number: PJ-002AH; SOURCE: DIGI CP-002AH-ND
J30 = CON12: Connector, 12 pin; CCA: 22; MFG: MOLEX; Part Number: 53398-1271; SOURCE: DIGI WM7616CT-ND
J40 = JUMPER-1x3: Jumper, 1x3; CCA: 129; MFG: HARWIN; Part Number: M22-2510305; SOURCE: DIGI 952-1312-ND
Q2 = 2N2222A: Transistor, Darlington NPN; CCA: 134; MFG: DIODES; Part Number: MMBT6427-7-F; RATING: 40V, 500mA; SOURCE: DIGI MMBT6427-FDICT-ND
Q3 = 2N2222A: Transistor, NPN; CCA: 133; MFG: FAIRCHILD; Part Number: MMBT2222A; RATING: 40V, 500mA; SOURCE: DIGI MMBT2222AFSCT-ND
R78 = R: Resistor; CCA: 65; ICA_MFR_NAME: PANASONIC; ICA_PARTNUM: $$1785048$$ERJ-3GSYJ102; MFG: PANASONIC; Part Number: ERJ-2GEJ103X; RATING: 1/10W; SOURCE: DIGI P10.0KLCT-ND; TOLERANCE: 5%
R144 = R: Resistor; CCA: 67; ICA_MFR_NAME: PANASONIC; ICA_PARTNUM: $$1785048$$ERJ-3GSYJ102; MFG: PANASONIC; Part Number: ERJ-2GEJ330X; RATING: 1/10W; SOURCE: DIGI P33JCT-ND; TOLERANCE: 5%
R666 R667 R670 = R: Resistor; CCA: 62; ICA_MFR_NAME: PANASONIC; ICA_PARTNUM: $$1785048$$ERJ-3GSYJ102; MFG: PANASONIC; Part Number: ERJ-2GE0R00X; RATING: 1/10W; SOURCE: DIGI P0.0JCT-ND
U10 U29 = PMD1000_0: IC, Power and Motor Driver; CCA: 140; MFG: TI; Part Number: DLPA100PT; SOURCE: PROVIDED BY TI
U27 = DSC1101_DSC1121: IC, Oscilator; CCA: 55; MFG: DISCERA; Part Number: DSC1101CI5-020.0000T
U28 = CDCLVC1102: IC, Fanout Buffer; CCA: 49; MFG: TI; Part Number: CDCLVC1102PW
U32 U33 = DDP442x: IC, ASIC; CCA: 54; MFG: TI; Part Number: DLPC4420ZPC; SOURCE: PROVIDED BY TI
C28 C535 = CAP_NP: Capacitor; CCA: 38; MFG: KEMET; Part Number: C0805C224K5RACTU; RATING: 25V; SOURCE: DIGI 399-3491-1-ND; TOLERANCE: 10%; Type: X7R
C56 C716 C746 = CAP_NP: Capacitor; CCA: 115; MFG: SAMSUNG; Part Number: CL32A476KOJNNNE; RATING: 16V; SOURCE: DIGI 490-3887-1-ND; TOLERANCE: 10%; Type: X5R
C522 C710 = CAP_NP: Capacitor; CCA: 16; MFG: AVX; Part Number: 12103D226KAT2A; RATING: 25V; SOURCE: DIGI 490-1882-2-ND; TOLERANCE: 10%; Type: X5R
C533 = CAP_NP: Capacitor; CCA: 42; MFG: TDK; Part Number: C2012X7R1E475K125AB; RATING: 25V; SOURCE: DIGI 445-5972-1-ND; TOLERANCE: 10%; Type: X7R
C548 C557 C586 C598 = CAP_NP: Capacitor; CCA: 113; MFG: SAMSUNG; Part Number: CL21B334KBFNNNE; RATING: 50V; SOURCE: DIGI 490-1677-1-ND; TOLERANCE: 10%; Type: X7R
D7 D13 D14 = DIODE_SCHOTTKY: Diode, Schottky; CCA: 27; MFG: DIODES INC; Part Number: B220A-13-F; RATING: 20V, 2A; SOURCE: DIGI B220A-FDICT-ND
D11 = DIODE: Diode; CCA: 136; MFG: ON SEMI; Part Number: MURS320T3G; RATING: 200V, 4A; SOURCE: DIGI MURS320T3GOSCT-ND
D506 = DIODE_SCHOTTKY: Diode, Schottky; CCA: 27; MFG: DIODES INC; Part Number: B340B-13-F; RATING: 40V, 3A; SOURCE: DIGIB340B-FDICT-ND
L9 = INDUCTOR: Inductor; CCA: 156; ICA_MFR_NAME: STEWARD; ICA_PARTNUM: $$731362$$MI0603J680R-10; MFG: BOURNS; Part Number: SRR1005-150M; RATING: 1.7A; SOURCE: DIGI SRR1005-150M-ND; TOLERANCE: 20%
L10 = INDUCTOR: Inductor; CCA: 154; ICA_MFR_NAME: STEWARD; ICA_PARTNUM: $$731362$$MI0603J680R-10; MFG: BOURNS; Part Number: SRR1005-4R7M; RATING: 2.5A; SOURCE: DIGI SRR1005-4R7M-ND; TOLERANCE: 20%
L13 L14 = INDUCTOR: Inductor; CCA: 155; ICA_MFR_NAME: STEWARD; ICA_PARTNUM: $$731362$$MI0603J680R-10; MFG: BOURNS; Part Number: SRR1005-100M; RATING: 2A; SOURCE: DIGI SRR1005-100M-ND; TOLERANCE: 20%
Q5 Q502 = NTD14NO3RT4_0: MOSFET, N-Channel; CCA: 138; MFG: ON SEMI; Part Number: NTD14N03RT4G; RATING: 25Vdss, 14A; SOURCE: DIGI NTD14N03RT4OSCT-ND
R74 R94 R101 R105 R536 R615 = R: Resistor; CCA: 176; ICA_MFR_NAME: PANASONIC; ICA_PARTNUM: $$1785048$$ERJ-3GSYJ102; MFG: VISHAY/DALE; Part Number: WSL0805R0100FEA; RATING: 1/8W; SOURCE: DIGI WSLA-.01CT-ND; TOLERANCE: 1%
R559 = R: Resistor; CCA: 103; ICA_MFR_NAME: PANASONIC; ICA_PARTNUM: $$1785048$$ERJ-3GSYJ102; MFG: PANASONIC; Part Number: ERJ-L06KF10CV; RATING: 1/8W; SOURCE: DIGI P100LLCT-ND; TOLERANCE: 1%
R562 R611 = R: Resistor; CCA: 58; ICA_MFR_NAME: PANASONIC; ICA_PARTNUM: $$1785048$$ERJ-3GSYJ102; MFG: PANASONIC; Part Number: ERA-2AEB162X; RATING: 1/16W; SOURCE: DIGI P1.6KDCCT-ND; TOLERANCE: 0.1%
R563 R576 R612 = R: Resistor; CCA: 59; ICA_MFR_NAME: PANASONIC; ICA_PARTNUM: $$1785048$$ERJ-3GSYJ102; MFG: PANASONIC; Part Number: ERA-2AEB202X; RATING: 1/16W; SOURCE: DIGI P2.0KDCCT-ND; TOLERANCE: 0.1%
R580 = R: Resistor; CCA: 60; ICA_MFR_NAME: PANASONIC; ICA_PARTNUM: $$1785048$$ERJ-3GSYJ102; MFG: PANASONIC; Part Number: ERA-2AEB751X; RATING: 1/16W; SOURCE: DIGI P750DCCT-ND; TOLERANCE: 0.1%

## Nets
GND: C9.1 C10.2 C11.1 C12.1 C13.1 C14.1 C15.1 C16.1 C19.1 C20.1 C21.2 C22.1 C24.2 C25.1 C50.2 C51.2 C56.1 C72.1 C73.1 C75.1 C76.1 C77.1 C78.1 C79.1 C80.1 C81.2 C82.2 C83.1 C84.1 C85.1 C86.1 C87.1 C95.1 C506.1 C512.1 C514.1 C515.1 C519.2 C521.1 C522.1 C525.2 C528.2 C531.2 C533.1 C535.2 C557.1 C584.1 C586.1 C598.1 C710.1 C716.1 C746.1 C768.1 C769.2 C770.1 C773.1 C777.2 C778.2 C780.2 C785.2 C786.2 C798.1 C799.1 C801.1 C814.1 C946.1 C948.1 C950.1 C951.1 D7.2(A) D8.1(CATHODE) D13.2(A) D14.2(A) D506.2(A) J22.GND1(2) J22.GND2(3) J30.11 J30.12 Q2.1(EMITTER) Q3.1(EMITTER) R41.1 R55.1 R57.2 R59.1 R76.1 R107.1 R111.2 R116.1 R519.1 R526.2 R562.2 R576.1 R611.1 R623.1 R632.2 R636.1 R731.2 TP8.1(SIG) TP12.1 TP500.1(SIG) U7.2(GND) U9.2(GND2) U9.3(GND3) U9.15(PAD) U10.7(GND) U10.19(GND) U10.44(GND) U13.AA2(GND) U13.AA5(GND) U13.AA26(GND) U13.AA29(GND) U13.AA30(GND) U13.AB1(GND) U13.AB2(GND) U13.AB3(GND) U13.AB4(GND) U13.AB27(GND) U13.AB28(GND) U13.AC2(GND) U13.AC5(GND) U13.AC8(GND) U13.AC11(GND) U13.AC14(GND) U13.AC17(GND) U13.AC20(GND) U13.AC23(GND) U13.AC26(GND) U13.AC29(GND) U13.AC30(GND) U13.AD1(GND) U13.AD2(GND) U13.AD3(GND) U13.AD4(GND) U13.AD27(GND) U13.AD28(GND) U13.AE1(GND) U13.AE2(GND) U13.AE3(GND) U13.AE28(GND) U13.AE29(GND) U13.AE30(GND) U13.AF3(GND) U13.AF5(GND) U13.AF8(GND) U13.AF11(GND) U13.AF14(GND) U13.AF17(GND) U13.AF20(GND) U13.AF23(GND) U13.AF26(GND) U13.AG1(GND) U13.AH29(GND) U13.AJ2(GND) U13.AJ5(GND) U13.AJ8(GND) U13.AJ11(GND) U13.AJ14(GND) U13.AJ17(GND) U13.AJ20(GND) U13.AJ23(GND) U13.AJ26(GND) U13.B2(GND) U13.B5(GND) U13.B8(GND) U13.B11(GND) U13.B14(GND) U13.B17(GND) U13.B20(GND) U13.B23(GND) U13.B26(GND) U13.B29(GND) U13.E2(GND) U13.E5(GND) U13.E8(GND) U13.E11(GND) U13.E14(GND) U13.E17(GND) U13.E20(GND) U13.E23(GND) U13.E26(GND) U13.E30(GND) U13.F3(GND) U13.F4(GND) U13.F27(GND) U13.F28(GND) U13.G1(GND) U13.G2(GND) U13.G5(GND) U13.G26(GND) U13.G29(GND) U13.G30(GND) U13.H1(GND) U13.H2(GND) U13.H3(GND) U13.H4(GND) U13.H8(GND) U13.H11(GND) U13.H14(GND) U13.H17(GND) U13.H20(GND) U13.H23(GND) U13.H27(GND) U13.H28(GND) U13.J2(GND) U13.J5(GND) U13.J26(GND) U13.J29(GND) U13.J30(GND) U13.K1(GND) U13.K2(GND) U13.K3(GND) U13.K27(GND) U13.K28(GND) U13.L2(GND) U13.L5(GND) U13.L6(GND) U13.L7(GND) U13.L10(GND) U13.L12(GND) U13.L14(GND) U13.L16(GND) U13.L18(GND) U13.L21(GND) U13.L24(GND) U13.L25(GND) U13.L26(GND) U13.L29(GND) U13.L30(GND) U13.M1(GND) U13.M2(GND) U13.M3(GND) U13.M7(GND) U13.M11(GND) U13.M13(GND) U13.M17(GND) U13.M19(GND) U13.M21(GND) U13.M24(GND) U13.M27(GND) U13.M28(GND) U13.N2(GND) U13.N5(GND) U13.N8(GND) U13.N9(GND) U13.N10(GND) U13.N12(GND) U13.N14(GND) U13.N16(GND) U13.N18(GND) U13.N20(GND) U13.N23(GND) U13.N24(GND) U13.N26(GND) U13.N29(GND) U13.N30(GND) U13.P1(GND) U13.P2(GND) U13.P3(GND) U13.P4(GND) U13.P6(GND) U13.P8(GND) U13.P11(GND) U13.P13(GND) U13.P15(GND) U13.P17(GND) U13.P19(GND) U13.P21(GND) U13.P23(GND) U13.P25(GND) U13.P27(GND) U13.P28(GND) U13.R1(GND) U13.R2(GND) U13.R5(GND) U13.R8(GND) U13.R9(GND) U13.R10(GND) U13.R12(GND) U13.R14(GND) U13.R16(GND) U13.R18(GND) U13.R20(GND) U13.R24(GND) U13.R29(GND) U13.R30(GND) U13.T1(GND) U13.T2(GND) U13.T3(GND) U13.T4(GND) U13.T11(GND) U13.T13(GND) U13.T15(GND) U13.T17(GND) U13.T19(GND) U13.T21(GND) U13.T23(GND) U13.T27(GND) U13.T28(GND) U13.U2(GND) U13.U5(GND) U13.U8(GND) U13.U9(GND) U13.U10(GND) U13.U12(GND) U13.U14(GND) U13.U16(GND) U13.U18(GND) U13.U20(GND) U13.U24(GND) U13.U26(GND) U13.U29(GND) U13.U30(GND) U13.V1(GND) U13.V2(GND) U13.V3(GND) U13.V4(GND) U13.V6(GND) U13.V11(GND) U13.V13(GND) U13.V15(GND) U13.V17(GND) U13.V19(GND) U13.V21(GND) U13.V23(GND) U13.V25(GND) U13.V27(GND) U13.V28(GND) U13.W1(GND) U13.W2(GND) U13.W7(GND) U13.W8(GND) U13.W9(GND) U13.W10(GND) U13.W14(GND) U13.W20(GND) U13.W24(GND) U13.W29(GND) U13.W30(GND) U13.Y1(GND) U13.Y2(GND) U13.Y3(GND) U13.Y4(GND) U13.Y5(GND) U13.Y6(GND) U13.Y7(GND) U13.Y8(GND) U13.Y9(GND) U13.Y11(GND) U13.Y14(GND) U13.Y17(GND) U13.Y19(GND) U13.Y22(GND) U13.Y23(GND) U13.Y24(GND) U13.Y25(GND) U13.Y26(GND) U13.Y27(GND) U13.Y28(GND) U18.4(PGND) U18.8(GND) U18.11(PAD) U20.2(GND2) U20.3(GND3) U20.15(PAD) U23.6(GND) U23.11(PAD) U24.12(GND) U24.21(PAD) U27.3(GND) U28.4(GND) U29.7(GND) U29.19(GND) U29.44(GND) U501.2(GND2) U501.3(GND3) U501.15(PAD) ; also on sheet 2 5 6 7 14 15 16 17 18 19 20 21 22 23 24 25 26 27 28 30 31 32 33 35 36
P5V_M: R74.1 TP7.1 ; also on sheet 16 17 23 26 30
P5V_S: C85.2 U24.10(BIAS) ; also on sheet 14
P12V: C11.2 C12.2 C15.2 C16.2 C24.1 C25.2 C50.1 C51.1 C84.2 C86.2 C506.2 C512.2 C548.2 C557.2 C586.2 C598.2 FB1.2 J30.1 J30.2 R39.2 R60.2 R77.1 R80.1 R81.1 R559.2 TP9.1 TP11.1 U7.4(VIN) U9.4(PVIN4) U9.5(PVIN5) U9.6(VIN) U10.22(VBB1) U10.27(ISENK) U10.37(VBB2) U10.42(VBB4) U20.4(PVIN4) U20.5(PVIN5) U20.6(VIN) U501.4(PVIN4) U501.5(PVIN5) U501.6(VIN) ; also on sheet 2 14 15 16 24 26 33
P12V_IN: C22.2 FB1.1 J22.P12V_IN(1)
A1P8V_M: R536.1 ; also on sheet 27
A1P8V_SENSE: C533.2 R536.2 R563.1 TP10.1 U10.29(VLIN1)
CW_INDEX1: U33.AF7(CW_INDEX) ; also on sheet 16 25
CW_INDEX3: J30.6 U32.AF7(CW_INDEX)
CW_PWM1: U33.AD8(CW_PWM) ; also on sheet 15
CW_PWM3: J30.5 U32.AD8(CW_PWM)
DA0: R689.1 U33.AB8(DADADDR_0)
DA1: R153.1 U33.AF4(DADADDR_1)
DA2: R151.1 U33.AE5(DADADDR_2)
DA3: R701.1 U33.AD6(DADADDR_3)
DADADD0: R689.2 ; also on sheet 2
DADADD1: R153.2 ; also on sheet 2
DADADD2: R151.2 ; also on sheet 2
DADADD3: R701.2 ; also on sheet 2
DADINTZ: R686.2 R730.2 ; also on sheet 2
DADMD0: R148.2 ; also on sheet 2
DADMD1: R699.2 ; also on sheet 2
DADOEZ: R698.2 R732.2 ; also on sheet 2
DADSEL0: R700.2 ; also on sheet 2
DADSEL1: R156.2 ; also on sheet 2
DADSTB: R150.2 TP38.1 ; also on sheet 2
DDR_VREF: C81.1 R110.2 R111.1 U18.6(REFOUT) ; also on sheet 5 6 32
DDR_VTT: C75.2 C76.2 C77.2 U18.3(VO) U18.5(VOSNS) ; also on sheet 5 6
DINTZ: R686.1 U33.AC8(DAD_INTZ)
DM0: R148.1 U33.AE6(DADMODE_0)
DM1: R699.1 U33.AD7(DADMODE_1)
DMD_P3P3V: C946.2 C948.2 FB519.1 FB520.1 R730.1 R732.1 R733.2 ; also on sheet 14 36
DMDP3P3VA: C951.2 FB520.2 ; also on sheet 2
DMDP3P3VB: C950.2 FB519.2 ; also on sheet 2
DMDSPARE0: R731.1 ; also on sheet 2
DOEZ: R698.1 U33.AE7(DADOEZ)
DS0: R700.1 U33.AC7(DADSEL_0)
DS1: R156.1 U33.AE4(DADSEL_1)
DSTB: R150.1 U33.AF5(DADSTRB)
EXT_ARSTZ: R646.2 TP23.1 U33.T24(EXT_RSTZ) ; also on sheet 2 16 33
FAN1_SW: U10.40(F1SW) ; also on sheet 16
FAN2_SW: U10.39(F2SW) ; also on sheet 16
FAN3_SW: U10.38(F3SW) ; also on sheet 16
FAN4_SW: U29.40(F1SW) ; also on sheet 16
FAN5_SW: J40.1 U29.39(F2SW) ; also on sheet 16
FAN6_SW: J40.3 ; also on sheet 16
FAN6_SW_JUMP: J40.2 U29.38(F3SW)
M_CLK: U28.3(Y0) U33.M26(MOSCP)
M_DCLKA_N: U33.J4(DCKB_N) ; also on sheet 2
M_DCLKA_P: U33.J3(DCKB_P) ; also on sheet 2
M_DCLKB_N: U33.V3(DCKA_N) ; also on sheet 2
M_DCLKB_P: U33.V4(DCKA_P) ; also on sheet 2
M_DDA00_N: U33.N2(DDB_N_15) ; also on sheet 2
M_DDA00_P: U33.N1(DDB_P_15) ; also on sheet 2
M_DDA01_N: U33.N4(DDB_N_14) ; also on sheet 2
M_DDA01_P: U33.N3(DDB_P_14) ; also on sheet 2
M_DDA02_N: U33.M1(DDB_N_13) ; also on sheet 2
M_DDA02_P: U33.M2(DDB_P_13) ; also on sheet 2
M_DDA03_N: U33.M4(DDB_N_12) ; also on sheet 2
M_DDA03_P: U33.M3(DDB_P_12) ; also on sheet 2
M_DDA04_N: U33.L2(DDB_N_11) ; also on sheet 2
M_DDA04_P: U33.L1(DDB_P_11) ; also on sheet 2
M_DDA05_N: U33.L4(DDB_N_10) ; also on sheet 2
M_DDA05_P: U33.L3(DDB_P_10) ; also on sheet 2
M_DDA06_N: U33.K2(DDB_N_9) ; also on sheet 2
M_DDA06_P: U33.K1(DDB_P_9) ; also on sheet 2
M_DDA07_N: U33.K4(DDB_N_8) ; also on sheet 2
M_DDA07_P: U33.K3(DDB_P_8) ; also on sheet 2
M_DDA08_N: U33.H2(DDB_N_7) ; also on sheet 2
M_DDA08_P: U33.H1(DDB_P_7) ; also on sheet 2
M_DDA09_N: U33.H4(DDB_N_6) ; also on sheet 2
M_DDA09_P: U33.H3(DDB_P_6) ; also on sheet 2
M_DDA10_N: U33.G2(DDB_N_5) ; also on sheet 2
M_DDA10_P: U33.G1(DDB_P_5) ; also on sheet 2
M_DDA11_N: U33.G4(DDB_N_4) ; also on sheet 2
M_DDA11_P: U33.G3(DDB_P_4) ; also on sheet 2
M_DDA12_N: U33.F2(DDB_N_3) ; also on sheet 2
M_DDA12_P: U33.F1(DDB_P_3) ; also on sheet 2
M_DDA13_N: U33.F4(DDB_N_2) ; also on sheet 2
M_DDA13_P: U33.F3(DDB_P_2) ; also on sheet 2
M_DDA14_N: U33.E2(DDB_N_1) ; also on sheet 2
M_DDA14_P: U33.E1(DDB_P_1) ; also on sheet 2
M_DDA15_N: U33.D2(DDB_N_0) ; also on sheet 2
M_DDA15_P: U33.D1(DDB_P_0) ; also on sheet 2
M_DDB00_N: U33.P3(DDA_N_15) ; also on sheet 2
M_DDB00_P: U33.P4(DDA_P_15) ; also on sheet 2
M_DDB01_N: U33.P1(DDA_N_14) ; also on sheet 2
M_DDB01_P: U33.P2(DDA_P_14) ; also on sheet 2
M_DDB02_N: U33.R3(DDA_N_13) ; also on sheet 2
M_DDB02_P: U33.R4(DDA_P_13) ; also on sheet 2
M_DDB03_N: U33.R1(DDA_N_12) ; also on sheet 2
M_DDB03_P: U33.R2(DDA_P_12) ; also on sheet 2
M_DDB04_N: U33.T3(DDA_N_11) ; also on sheet 2
M_DDB04_P: U33.T4(DDA_P_11) ; also on sheet 2
M_DDB05_N: U33.T1(DDA_N_10) ; also on sheet 2
M_DDB05_P: U33.T2(DDA_P_10) ; also on sheet 2
M_DDB06_N: U33.U3(DDA_N_9) ; also on sheet 2
M_DDB06_P: U33.U4(DDA_P_9) ; also on sheet 2
M_DDB07_N: U33.U1(DDA_N_8) ; also on sheet 2
M_DDB07_P: U33.U2(DDA_P_8) ; also on sheet 2
M_DDB08_N: U33.W3(DDA_N_7) ; also on sheet 2
M_DDB08_P: U33.W4(DDA_P_7) ; also on sheet 2
M_DDB09_N: U33.W1(DDA_N_6) ; also on sheet 2
M_DDB09_P: U33.W2(DDA_P_6) ; also on sheet 2
M_DDB10_N: U33.Y1(DDA_N_5) ; also on sheet 2
M_DDB10_P: U33.Y2(DDA_P_5) ; also on sheet 2
M_DDB11_N: U33.Y3(DDA_N_4) ; also on sheet 2
M_DDB11_P: U33.Y4(DDA_P_4) ; also on sheet 2
M_DDB12_N: U33.AA1(DDA_N_3) ; also on sheet 2
M_DDB12_P: U33.AA2(DDA_P_3) ; also on sheet 2
M_DDB13_N: U33.AA3(DDA_N_2) ; also on sheet 2
M_DDB13_P: U33.AA4(DDA_P_2) ; also on sheet 2
M_DDB14_N: U33.AB1(DDA_N_1) ; also on sheet 2
M_DDB14_P: U33.AB2(DDA_P_1) ; also on sheet 2
M_DDB15_N: U33.AC1(DDA_N_0) ; also on sheet 2
M_DDB15_P: U33.AC2(DDA_P_0) ; also on sheet 2
M_SCTRLA_N: U33.J2(SCB_N) ; also on sheet 2
M_SCTRLA_P: U33.J1(SCB_P) ; also on sheet 2
M_SCTRLB_N: U33.V1(SCA_N) ; also on sheet 2
M_SCTRLB_P: U33.V2(SCA_P) ; also on sheet 2
MTR_ARSTZ: J30.3 R95.2 TP22.1 U10.48(RESETZ) U29.48(RESETZ) U33.T25(MTR_ARSTZ)
OCLKA: R144.1 ; also on sheet 15
OCLKA_RES: R144.2 U33.AF6(OCLKA)
P1P1V: C21.1 L501.1 R70.1 R527.1 ; also on sheet 7
P1P1V_FIL: C528.1 L501.2 ; also on sheet 7
P1P1V_M: C56.2 R94.2 R580.2 TP14.1 ; also on sheet 27
P1P1V_PWRGD: R62.1 U9.10(EN) U20.10(EN) U501.14(PWRGD)
P1P5V: C72.2 C73.2 R104.1 R108.1 R110.1 R622.2 U18.2(VLDOIN) ; also on sheet 5 6 25 32 33
P1P5V_FIL: C79.2 R113.1 R634.2 ; also on sheet 7 30
P1P5V_PWRGD: R624.1 U18.7(EN) U20.14(PWRGD)
P1P8V_M: R615.1 TP15.1 ; also on sheet 27
P1P15V: C525.1 L502.1 R72.1 R75.2 ; also on sheet 30
P1P15V_FIL: C531.1 L502.2 ; also on sheet 30
P2P5V: C80.2 C82.1 C777.1 L503.1 R114.2 R115.1 U23.1(IN) U23.2(IN) ; also on sheet 7 32 33
P2P5V_FIL: C778.1 L503.2 ; also on sheet 7 30
P2P5V_M: Q502.2(D2) Q502.4(D4) R105.2 TP17.1
P2P5V_PWRGD: R635.1 U23.5(EN) U24.9(PWRGD)
P3P0V: R59.2 R60.1 R62.2 R525.2 R624.2 U501.10(EN)
P3P3V: C83.2 C87.2 C780.1 C785.1 R73.1 R518.1 R635.2 U18.10(VIN) U23.4(BIAS) U24.5(IN_1) U24.6(IN_2) U24.7(IN_3) U24.8(IN_4) U24.15(SS) ; also on sheet 7 25 30 31 33
P3P3V_M: FB2.1 FB503.2 R95.1 R101.2 R588.1 R593.1 R598.1 R646.1 TP16.1 ; also on sheet 14 15 16 17 18 20 21 23 24 27 30 35
P3P3V_PWRGD: R525.1 U9.14(PWRGD) U24.11(EN)
P3P3V_S: R142.1 ; also on sheet 14 15 19 22 25 26 28
P_INTZ: R670.1 U29.36(PMDINTZ)
PGOOD: R667.1 U29.35(PWRGOOD)
PMD1K_CP1: C28.1 U10.18(CP1)
PMD1K_CP2: C28.2 U10.17(CP2)
PMD1K_FB_LIN1: R562.1 R563.2 U10.31(FB1)
PMD1K_FB_P2P5V: C746.2 L14.2 R105.1 U10.46(V2P5)
PMD1K_FB_P3P3V: C710.2 L13.2 R101.1 U10.45(V3P3)
PMD1K_FB_P5V: C522.2 L9.1 R74.2 U10.24(V5)
PMD1K_GD_CORE: Q5.1(G) U10.26(GDC)
PMD1K_VCP: C548.1 U10.21(VCP)
PMD1K_VREG: C535.1 U10.20(VREG) U10.47(TRIM)
PMD_INTZ: J30.4 R78.1 R598.2 R670.2 U10.36(PMDINTZ) U33.AE8(PMD_INTZ)
POSENSE: R588.2 R652.1 R661.1 R666.2 U10.34(POSENSE) ; also on sheet 21
POSENSE_FIL: C799.2 R652.2 U33.P22(POSENSE)
PSENS: R666.1 U29.34(POSENSE)
PWRGOOD: R593.2 R667.2 U10.35(PWRGOOD) U32.T26(PWRGOOD) U33.T26(PWRGOOD) ; also on sheet 18 21 30
S_CLK: U28.8(Y1) U32.M26(MOSCP)
S_POSENSE_FIL: C801.2 R661.2 U32.P22(POSENSE)
S_SSP2_CLK: J30.8 ; also on sheet 25
S_SSP2_CSZ0: J30.9 ; also on sheet 25
S_SSP2_DI: J30.10 ; also on sheet 25
S_SSP2_DO: J30.7 ; also on sheet 25
SSP0_CLK_PMD1: C584.2 U10.2(CLK) ; also on sheet 20
SSP0_CLK_PMD2: C814.2 U29.2(CLK) ; also on sheet 20
SSP0_CSZ2_PMD1: U10.4(CSZ) ; also on sheet 20
SSP0_CSZ3_PMD2: U29.4(CSZ) ; also on sheet 20
SSP0_RXD: R586.1 R665.1 R733.1 ; also on sheet 2 20 25
SSP0_TXD: U10.3(DIN) U29.3(DIN) ; also on sheet 20 25
SWNODE_CORE: D506.1(C) L10.1 Q5.3(S) U10.25(LXC)
SWNODE_P2P5V: D14.1(C) L14.1 U10.41(LX25)
SWNODE_P3P3V: D13.1(C) L13.1 U10.43(LX33)
SWNODE_P5V: D7.1(C) L9.2 U10.23(LX5)
N16826457: Q2.3(COLLECTOR) R71.2
N16826574: Q2.2(BASE) Q3.3(COLLECTOR) R81.2
N16826745: Q3.2(BASE) R78.2
N16827292: R586.2 U10.1(DOUT)
N16827429: D8.2(ANODE) R77.2
N16827499: D9.2(ANODE) R80.2
N16827874: D9.1(CATHODE) R71.1
N16830205: R576.2 R580.1 U10.30(/FBC)
N16830232: Q5.2(D2) Q5.4(D4) R559.1 U10.28(ISEN)
N16830236: D11.2(A) L10.2
N16830372: D11.1(K) R94.1
N16830527: C716.2 Q502.3(S) R612.2 R615.2
N16830576: R611.2 R612.1 U10.32(FB2)
N16830606: Q502.1(G) U10.33(GD2)
N18136838: R665.2 U29.1(DOUT)
N18281002: R142.2 U32.AE8(PMD_INTZ)
N18326219: U27.4(OUT) U28.1(CLK_IN)
N18326228: C95.2 FB2.2 U27.1(EN) U27.6(VDD)
N18326252: C798.2 FB503.1 U28.2(1G) U28.6(VDD)
N18639599: R75.1 R76.2 U7.5(VSEN)
N18639722: R57.1 U501.1(RT/CLK)
N18639740: C10.1 R42.1 U501.8(COMP)
N18639742: C14.2 U501.9(SS/TR)
N18639744: C520.1 L500.1 U501.11(PH11) U501.12(PH12)
N18639786: R55.2 R70.2 U501.7(VSENSE)
N18639812: C9.2 R42.2
N18639893: C515.2 L500.2 R527.2
N18639973: L7.1 U7.3(OUT)
N18639979: C13.2 C20.2 L7.2 R72.2
N18640113: R39.1 R41.2 U7.1(EN)
N18640186: C520.2 U501.13(BOOT)
N18640237: C769.1 R620.1 U20.8(COMP)
N18640239: C770.2 U20.9(SS/TR)
N18640241: C74.1 L15.1 U20.11(PH11) U20.12(PH12)
N18640243: R632.1 U20.1(RT/CLK)
N18640289: C768.2 R620.2
N18640297: R107.2 R108.2 U20.7(VSENSE)
N18640367: C78.2 L15.2 R104.2
N18640456: C74.2 U20.13(BOOT)
N18641820: R114.1 R116.2 U24.16(FB)
N18641860: R115.2 U24.1(OUT) U24.18(OUT_2) U24.19(OUT_3) U24.20(OUT_4)
N18642007: R526.1 U9.1(RT/CLK)
N18642009: C17.1 L8.1 U9.11(PH11) U9.12(PH12)
N18642011: C521.2 U9.9(SS/TR)
N18642013: C519.1 R520.1 U9.8(COMP)
N18642039: R518.2 R519.2 U9.7(VSENSE)
N18642057: C514.2 R520.2
N18642122: C19.2 L8.2 R73.2
N18642269: C17.2 U9.13(BOOT)
N18642327: C786.1 U23.7(SS)
N18642380: R634.1 R636.2 U23.8(FB)
N18642410: R113.2 U23.9(OUT_1) U23.10(OUT_2)
N18642684: C773.2 R622.1 R623.2 U18.1(REFIN)

Not connected (* = marked no-connect by the designer): U18 9(PGOOD)*; U23 3(PG)*; U24 2(NC1)* 3(NC2)* 4(NC3)* 13(NC4)* 14(NC5)* 17(NC6)*; U27 2(NC2)* 5(NC5)*; U28 5(NC5)* 7(NC7)*; U32 AF6(OCLKA)* B23(GPIO_16)* C22(GPIO_17)* N26(MOSCN)* T24(EXT_RSTZ)* T25(MTR_ARSTZ)*; U33 B23(GPIO_16)* C22(GPIO_17)* N26(MOSCN)*

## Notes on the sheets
sheet 8
- 12V TO 1.1V @ 6A
- 12V TO 1.15V @ 500mA
- 12V TO 1.5V @ 3A
- FPGA - Regulators
- (C) COPYRIGHT 2023
         Texas Instruments
        All Rights Reserved
sheet 9
- Power Sequence
- 12V TO 3.3V @ 3A
- P1P5V
- (FPGA VCCIO)
- +0.75
- (DDR3 VDD)
- (DDR_VTT)
- (DDR_VREF)
- +12V
- P1P1V
- (FPGA VCCIO)
- P3P3V
- (FPGA VCCPD)
- P2P5V
- (FPGA VCCH)
- P1P5V
- (FPGA CORE)
- (FPGA VCCAUX)
- (FPGA VCCD FPLL)
- (FPGA VCCL,R,T)
- P1P15V
- 3.3V TO 2.5V @ 1.5A
- 1.5V TO 0.75V DDR_VTT & DDR_VREF
- 2.5V TO 1.5V @ 500mA
- DDR TERMINATION VOLTAGE
- FPGA - Regulators
- (C) COPYRIGHT 2023
         Texas Instruments
        All Rights Reserved
sheet 10
- FPGA - GND
- (C) COPYRIGHT 2023
         Texas Instruments
        All Rights Reserved
sheet 11
- DMD Interface is BUS & BIT Swappable
- Primary
- Primary Controller DMD Flex Interface
- (C) COPYRIGHT 2023
         Texas Instruments
        All Rights Reserved
sheet 12
- Note: See DLPC4420 datasheet for Dual
  DLPC4420  oscillator requirements on
  applications using DynamicBlack or
  BrightSync
- Secondary
- Optional Header for DLPA100 #3
- Note:
  Jumper Pin 1 to Pin 2 for High Current Fan 5 (Fan 6 Disabled)
  Jumper Pin 2 to Pin 3 for Fan 5 and Fan 6 normal current
  Default: Pin 2 to Pin 3
- Primary
- Input Power and DLPA100 / DLPC4420 Interface
- (C) COPYRIGHT 2023
         Texas Instruments
        All Rights Reserved
sheet 13
- NOTE:
  R620, R634, R69, R102, R131, R85 are used
  for current measurement and are not required for
  production units.
  R713, R100, R232, R638 and R685 are used for alternate
  lab supplies and are not required for production units.
- 4
- NOTE:
  Consult the DLPA100 Data Sheet for
  external component specifications.
- DPAK
- IMPORTANT NOTE:
  The PCB should be designed such that the
  specifications are not exceeded when the
  DLPC4420 is operated under the maximum current
  conditions specified in the DLPC4420 datasheet.
- 1
- 2
- 3
- 4
- DPAK
- 1
- 2
- 3
- Primary DLPA100 Power Supplies
- (C) COPYRIGHT 2023
         Texas Instruments
        All Rights Reserved
